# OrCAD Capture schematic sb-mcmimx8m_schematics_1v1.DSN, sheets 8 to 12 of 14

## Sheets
8 07. MIPI LCD: size A3; title: SBC-MCM-iMX8M   07. MIPI-LCD; rev: 2.0
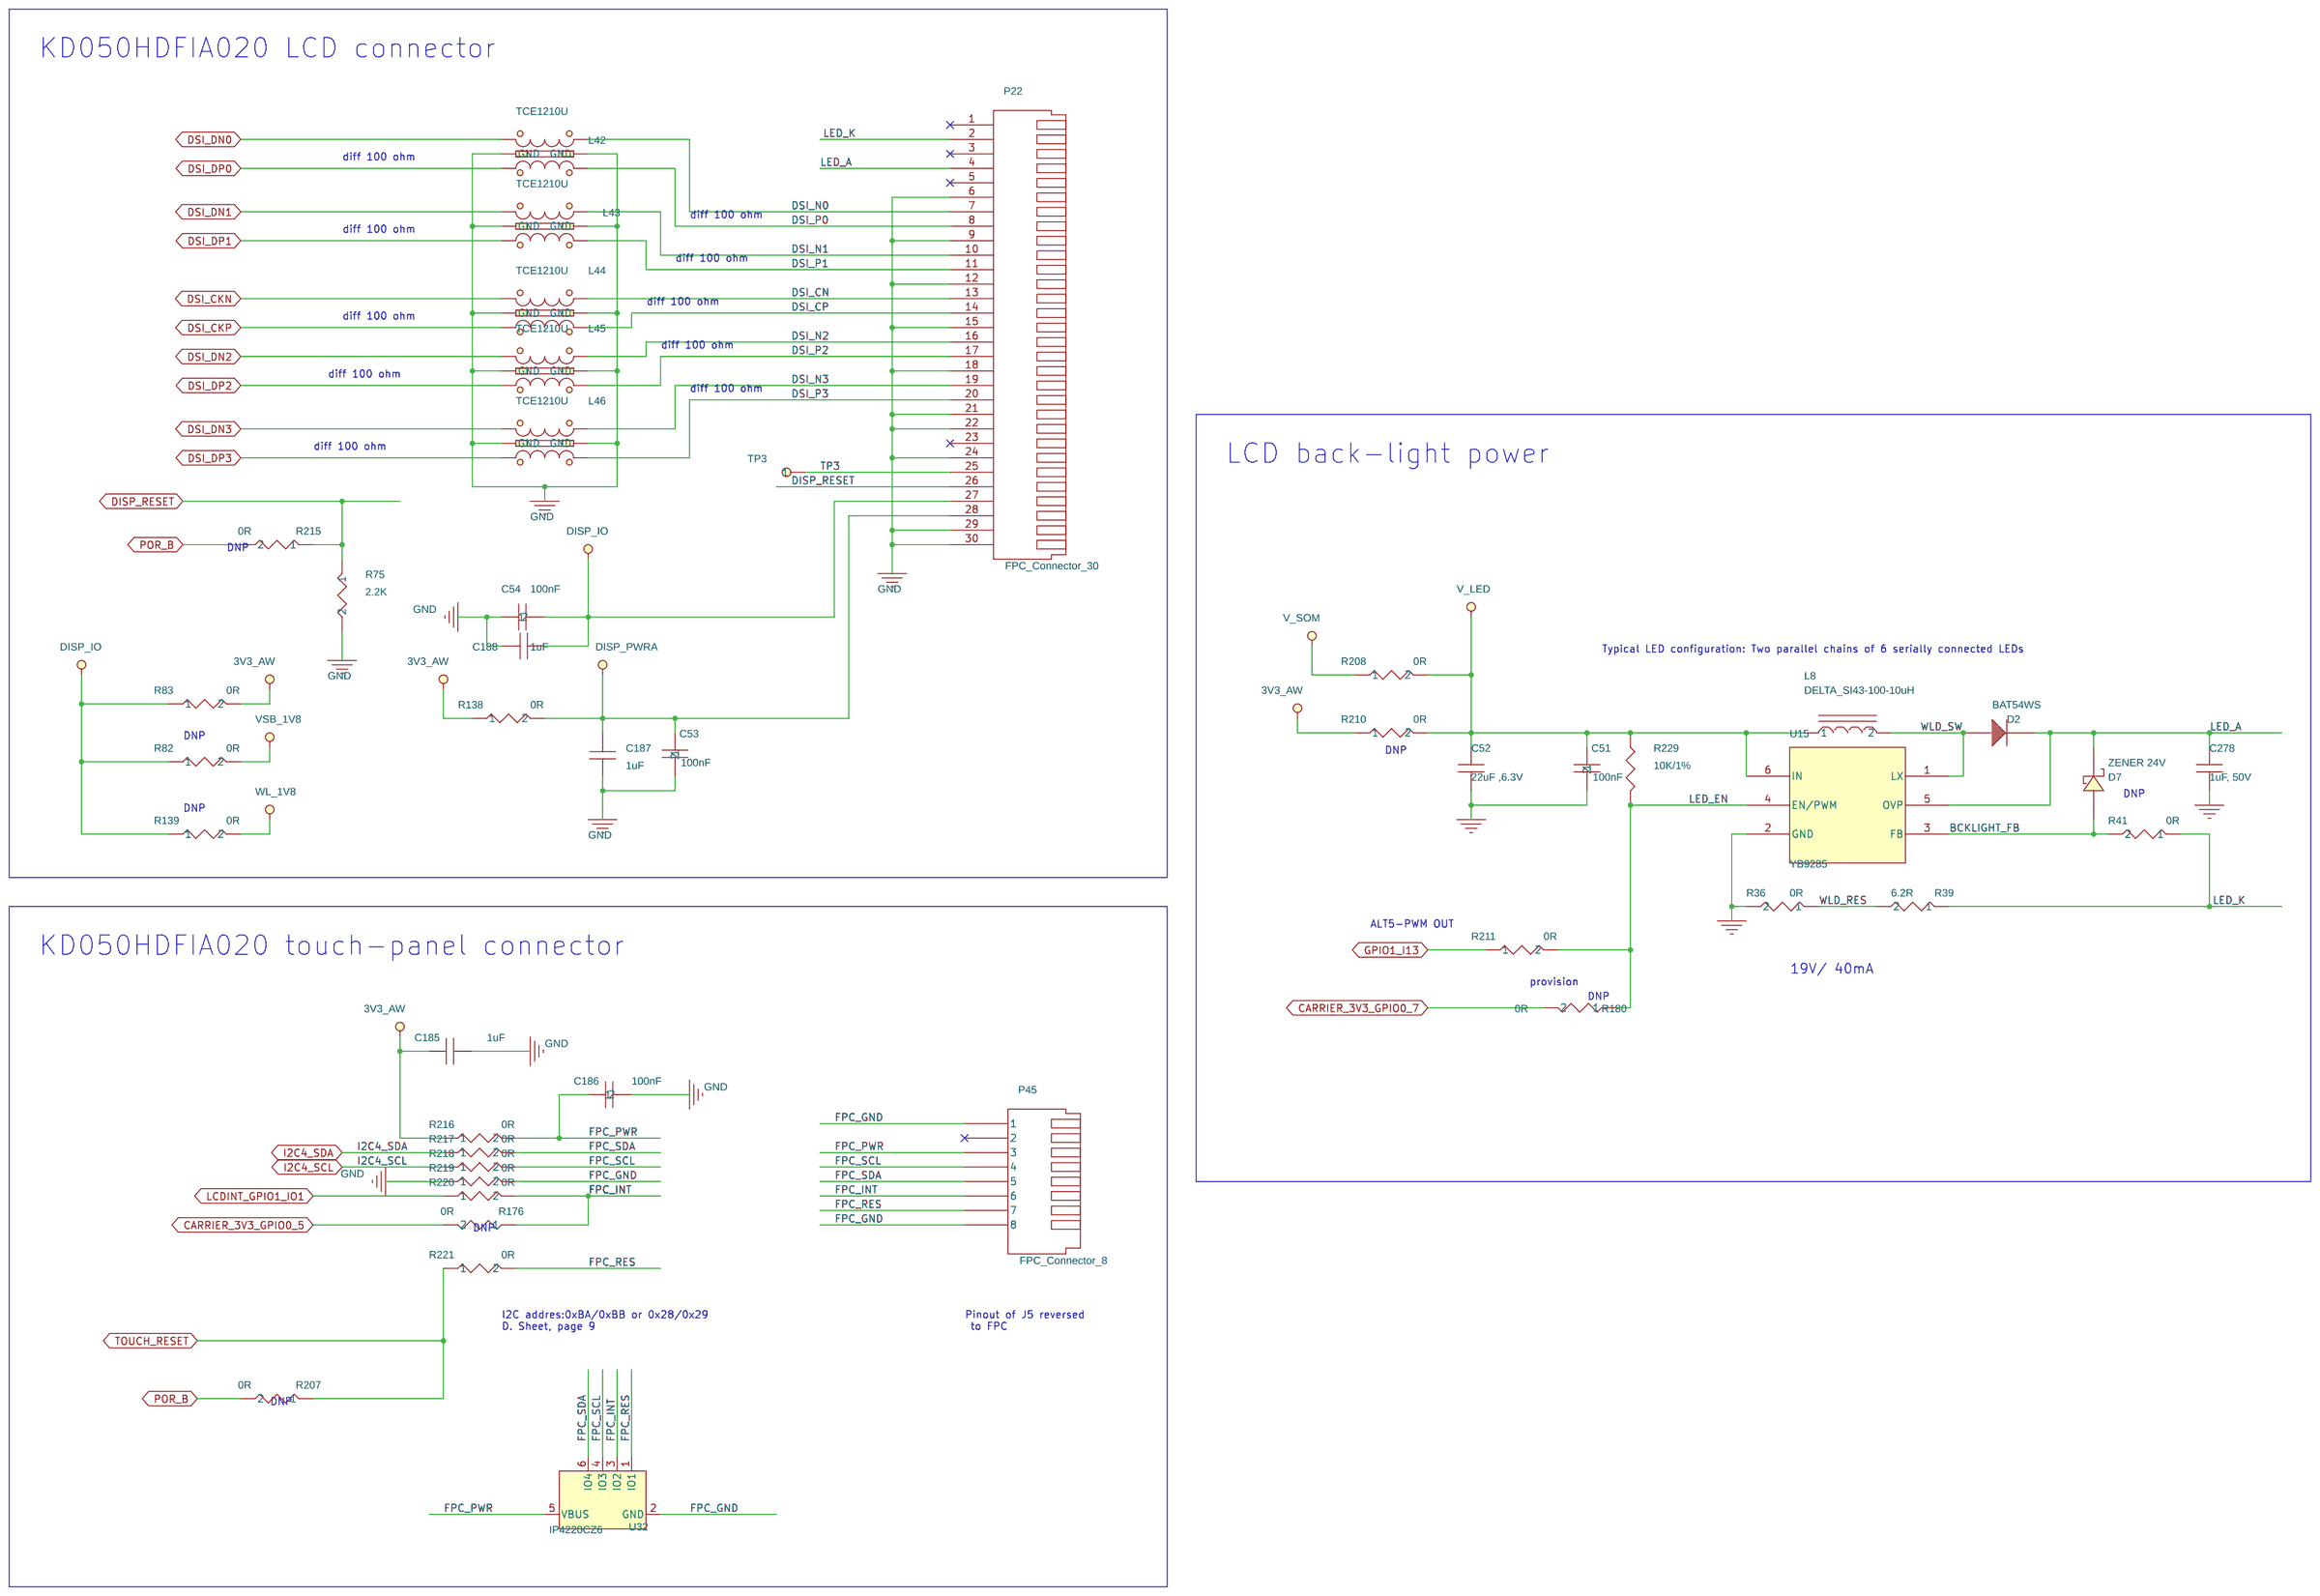
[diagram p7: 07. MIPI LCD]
9 08. PCIe: size A3; title: SB-UCM-iMX8M    08. PCIe; rev: 2.0
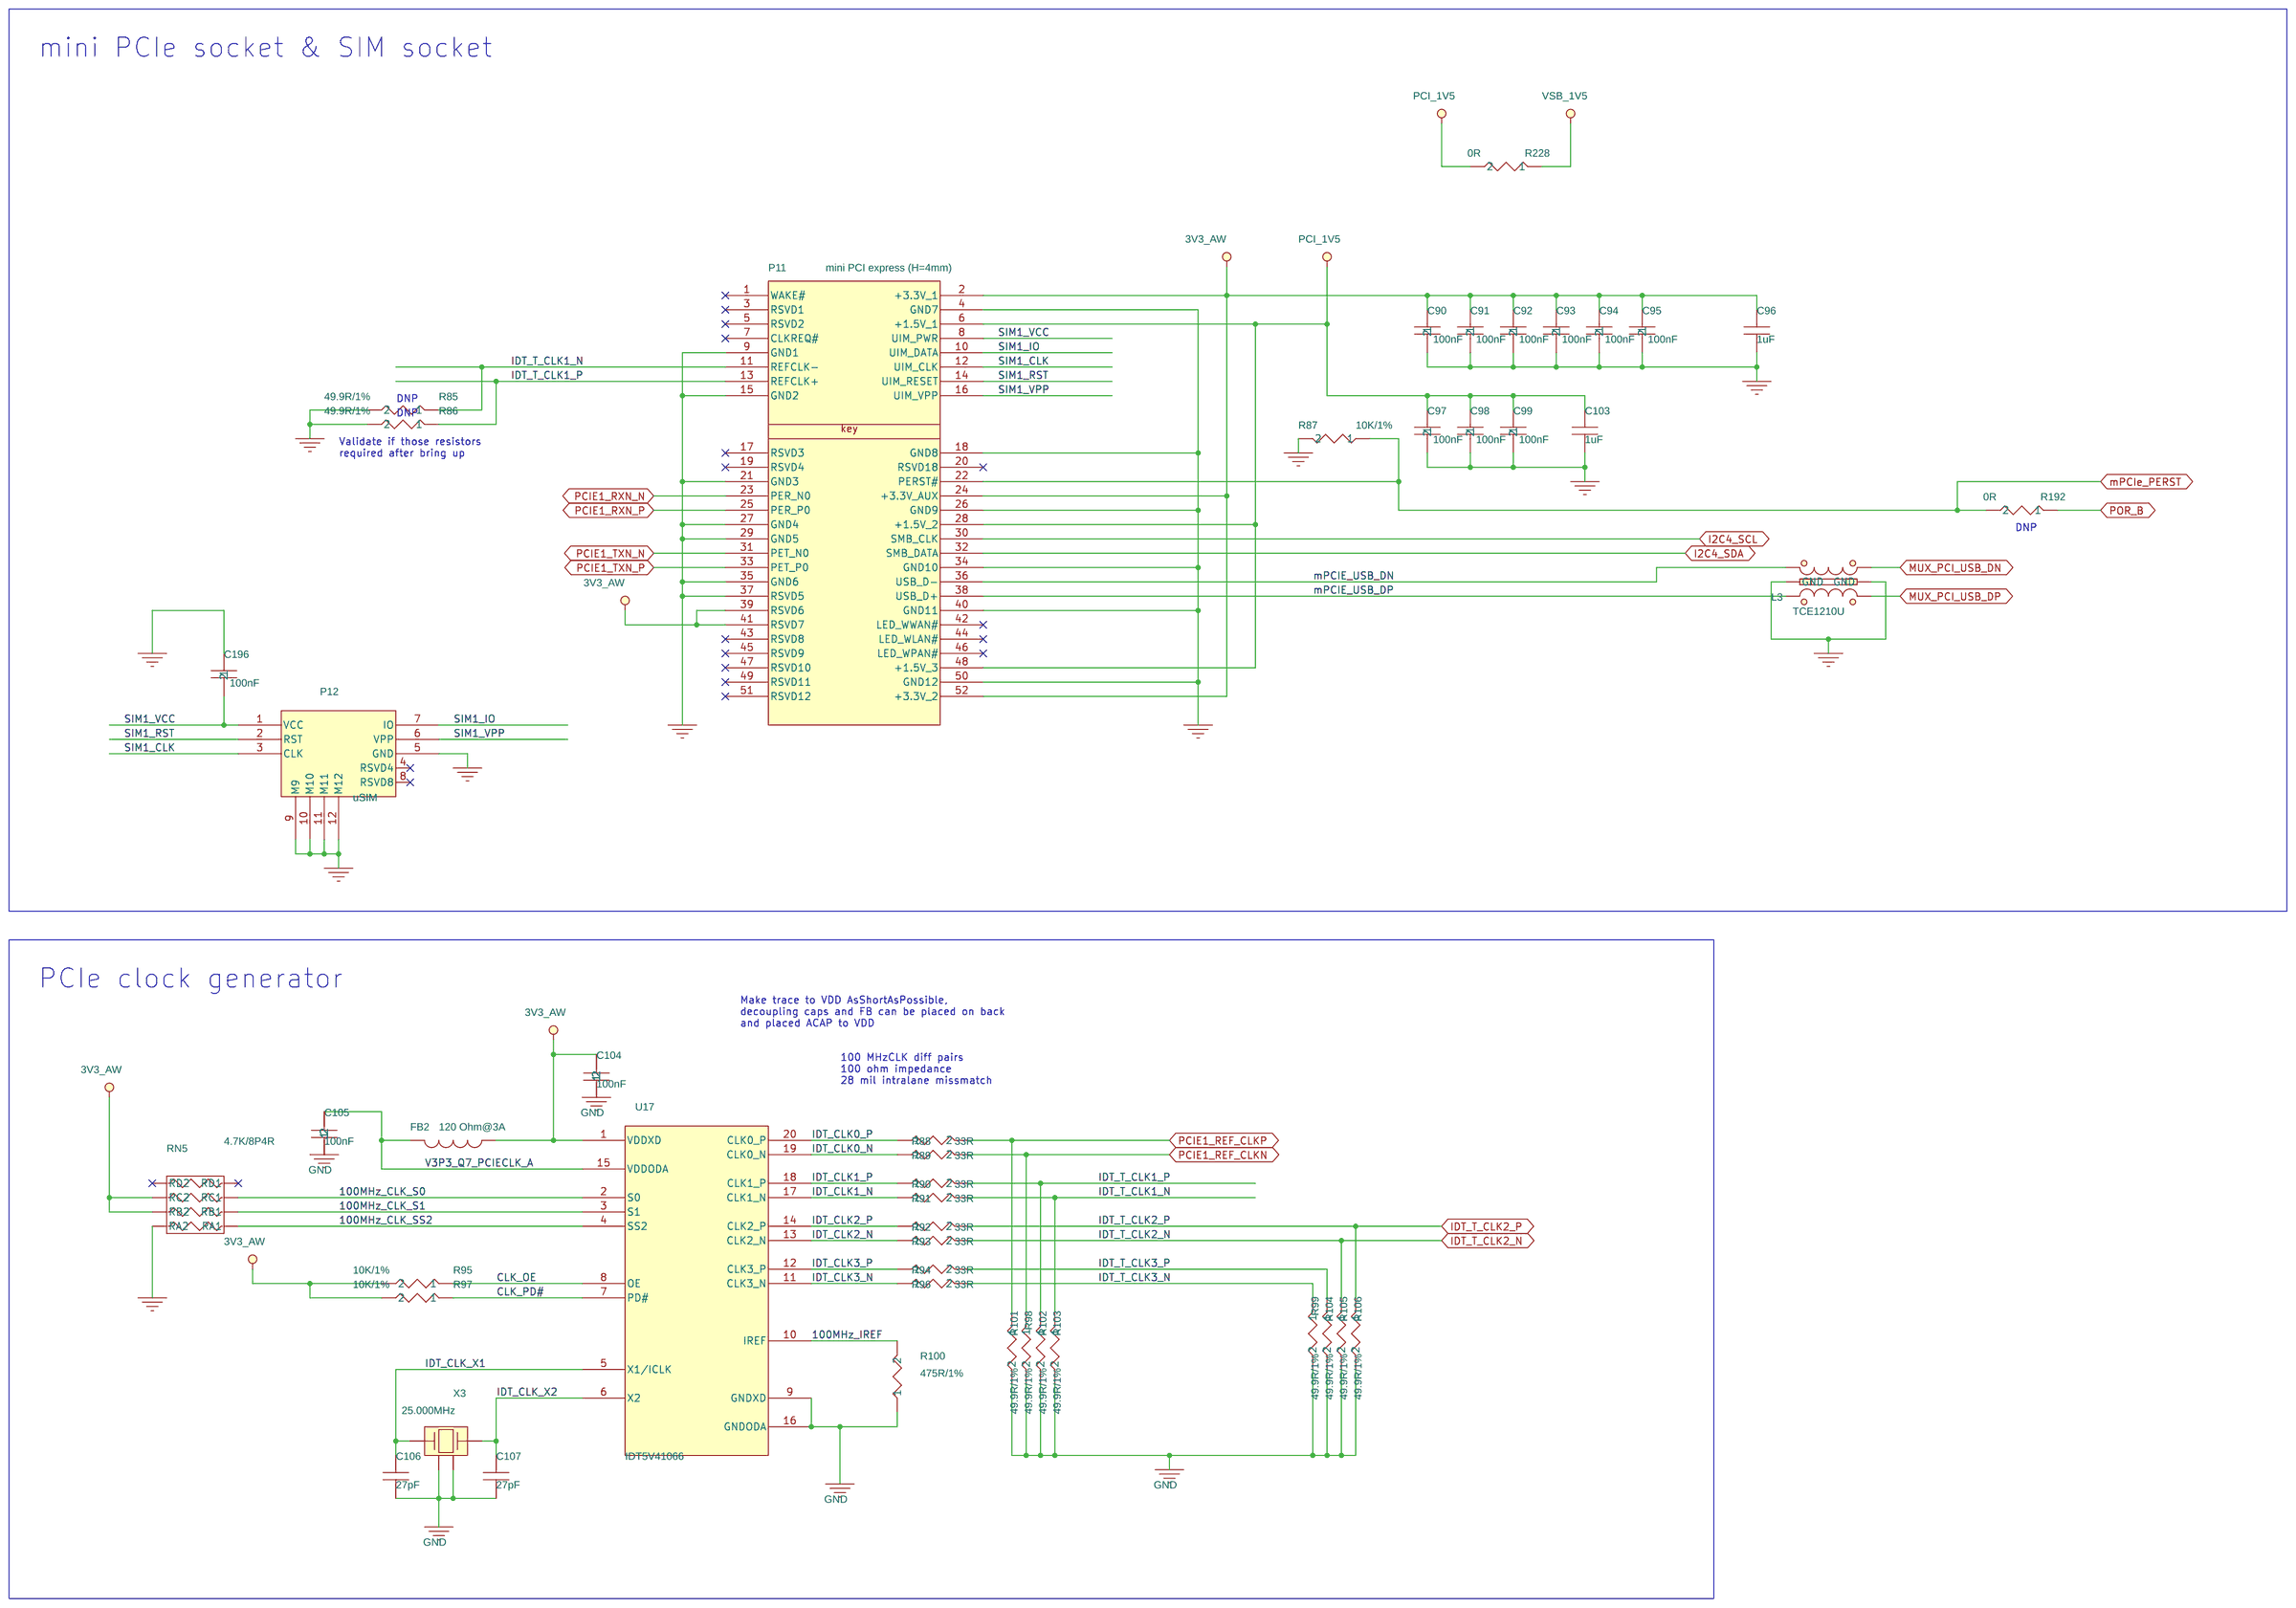
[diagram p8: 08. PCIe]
10 09. Power: size C; title: SBC-MCM-iMX8M    09. POWER; rev: 2.0
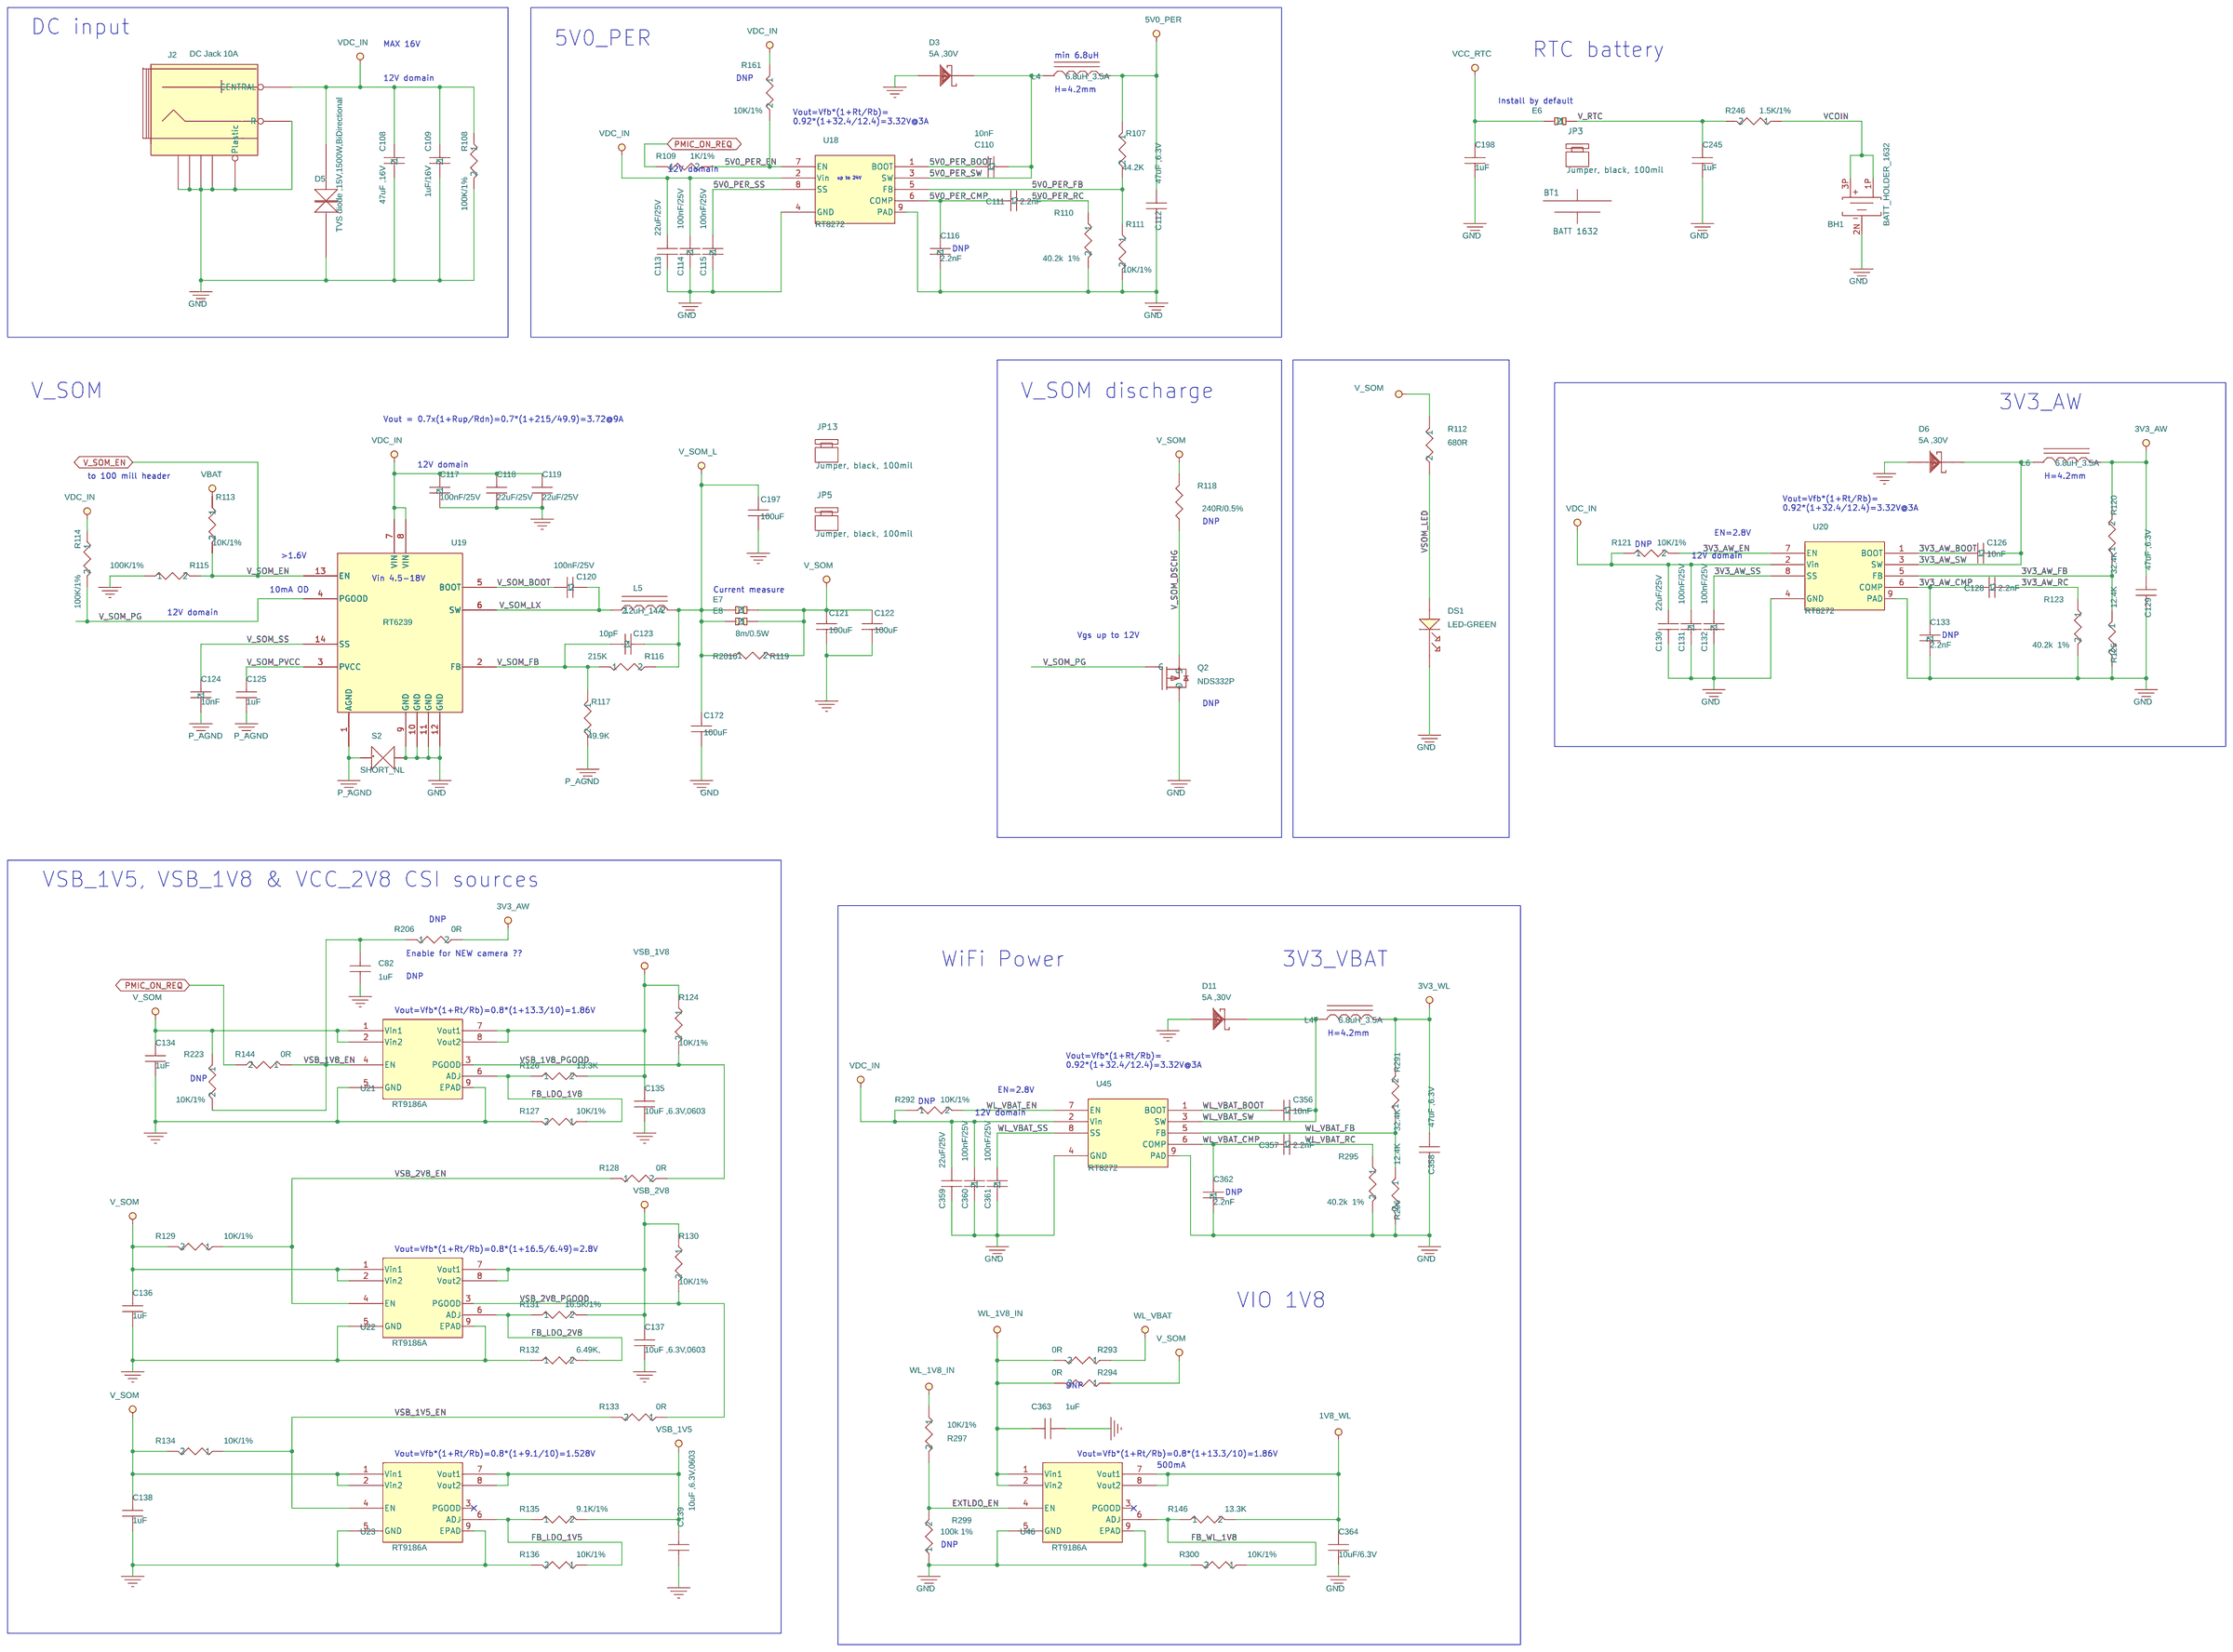
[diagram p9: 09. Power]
11 10. UART, RS232, SD, EPROM,QSPI: size C; title: SBC-MCM-iMX8M      10. UART, RS232, SD Slot, EEPROM,QSPI; rev: 2.0
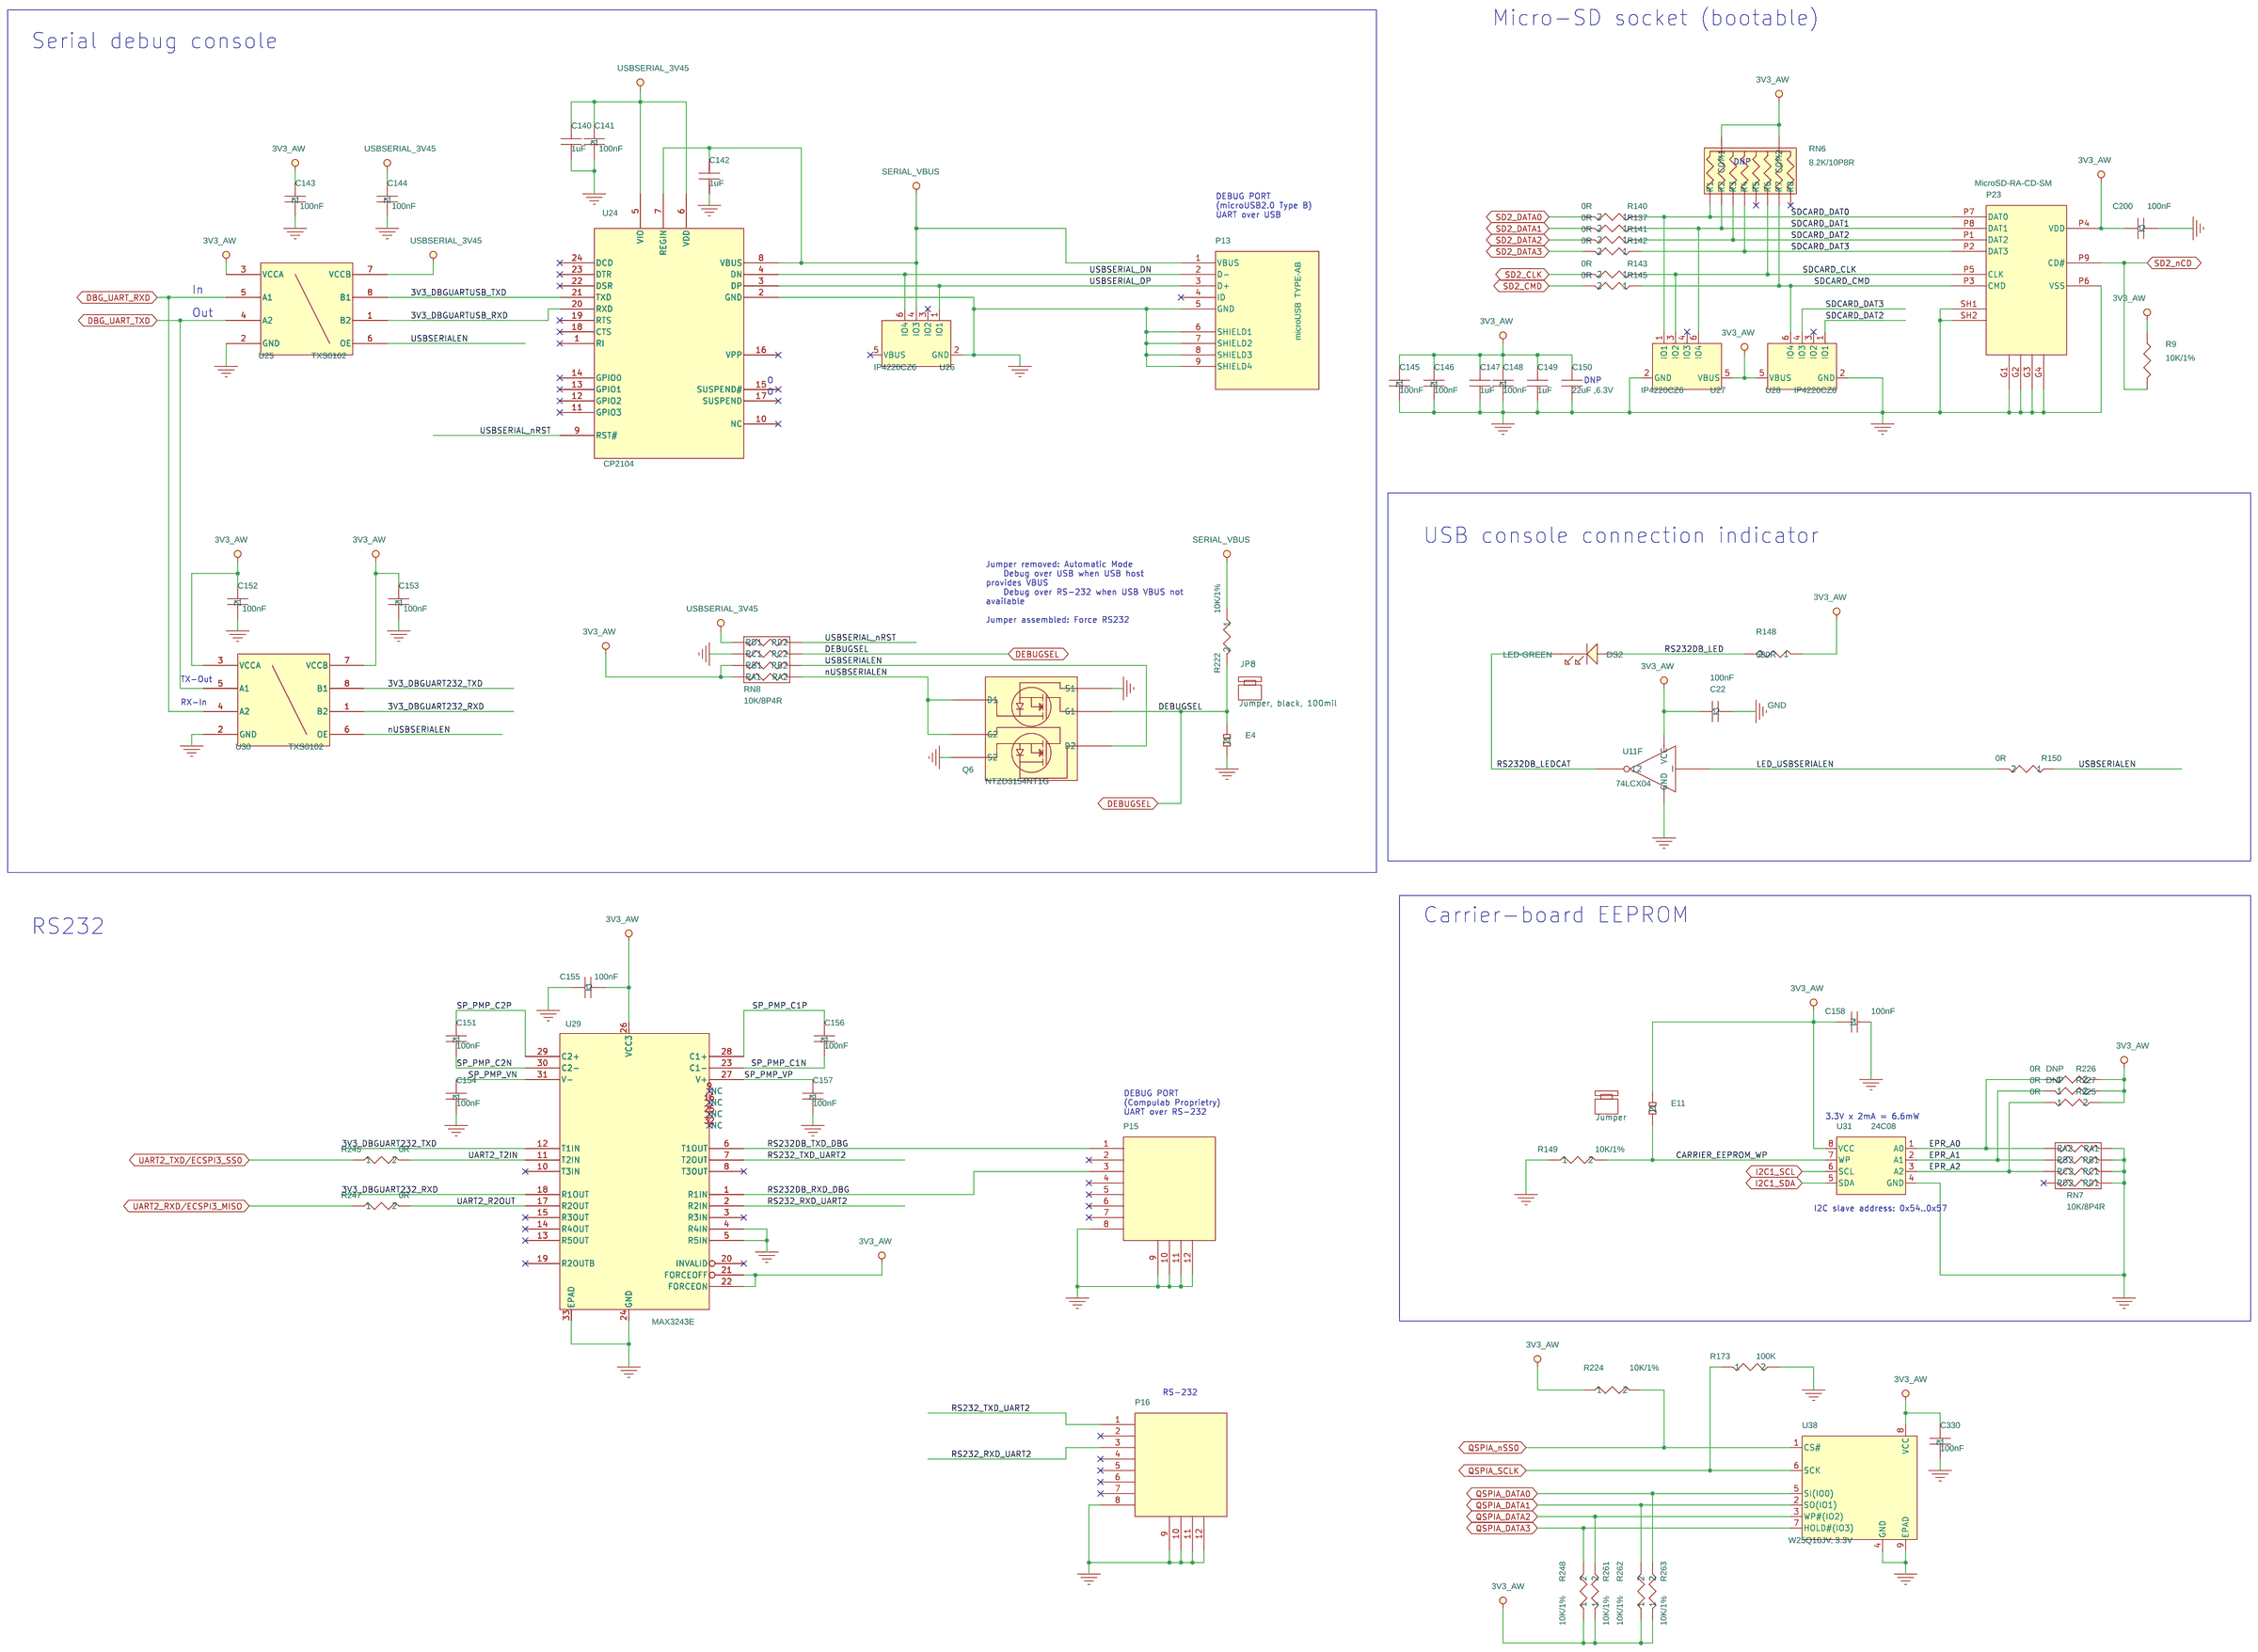
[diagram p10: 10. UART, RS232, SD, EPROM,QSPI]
12 11.WIFI&Bluetooth, RS485: size A2; title: SBC-MCM-iMX8M     11. WLAN,RS485
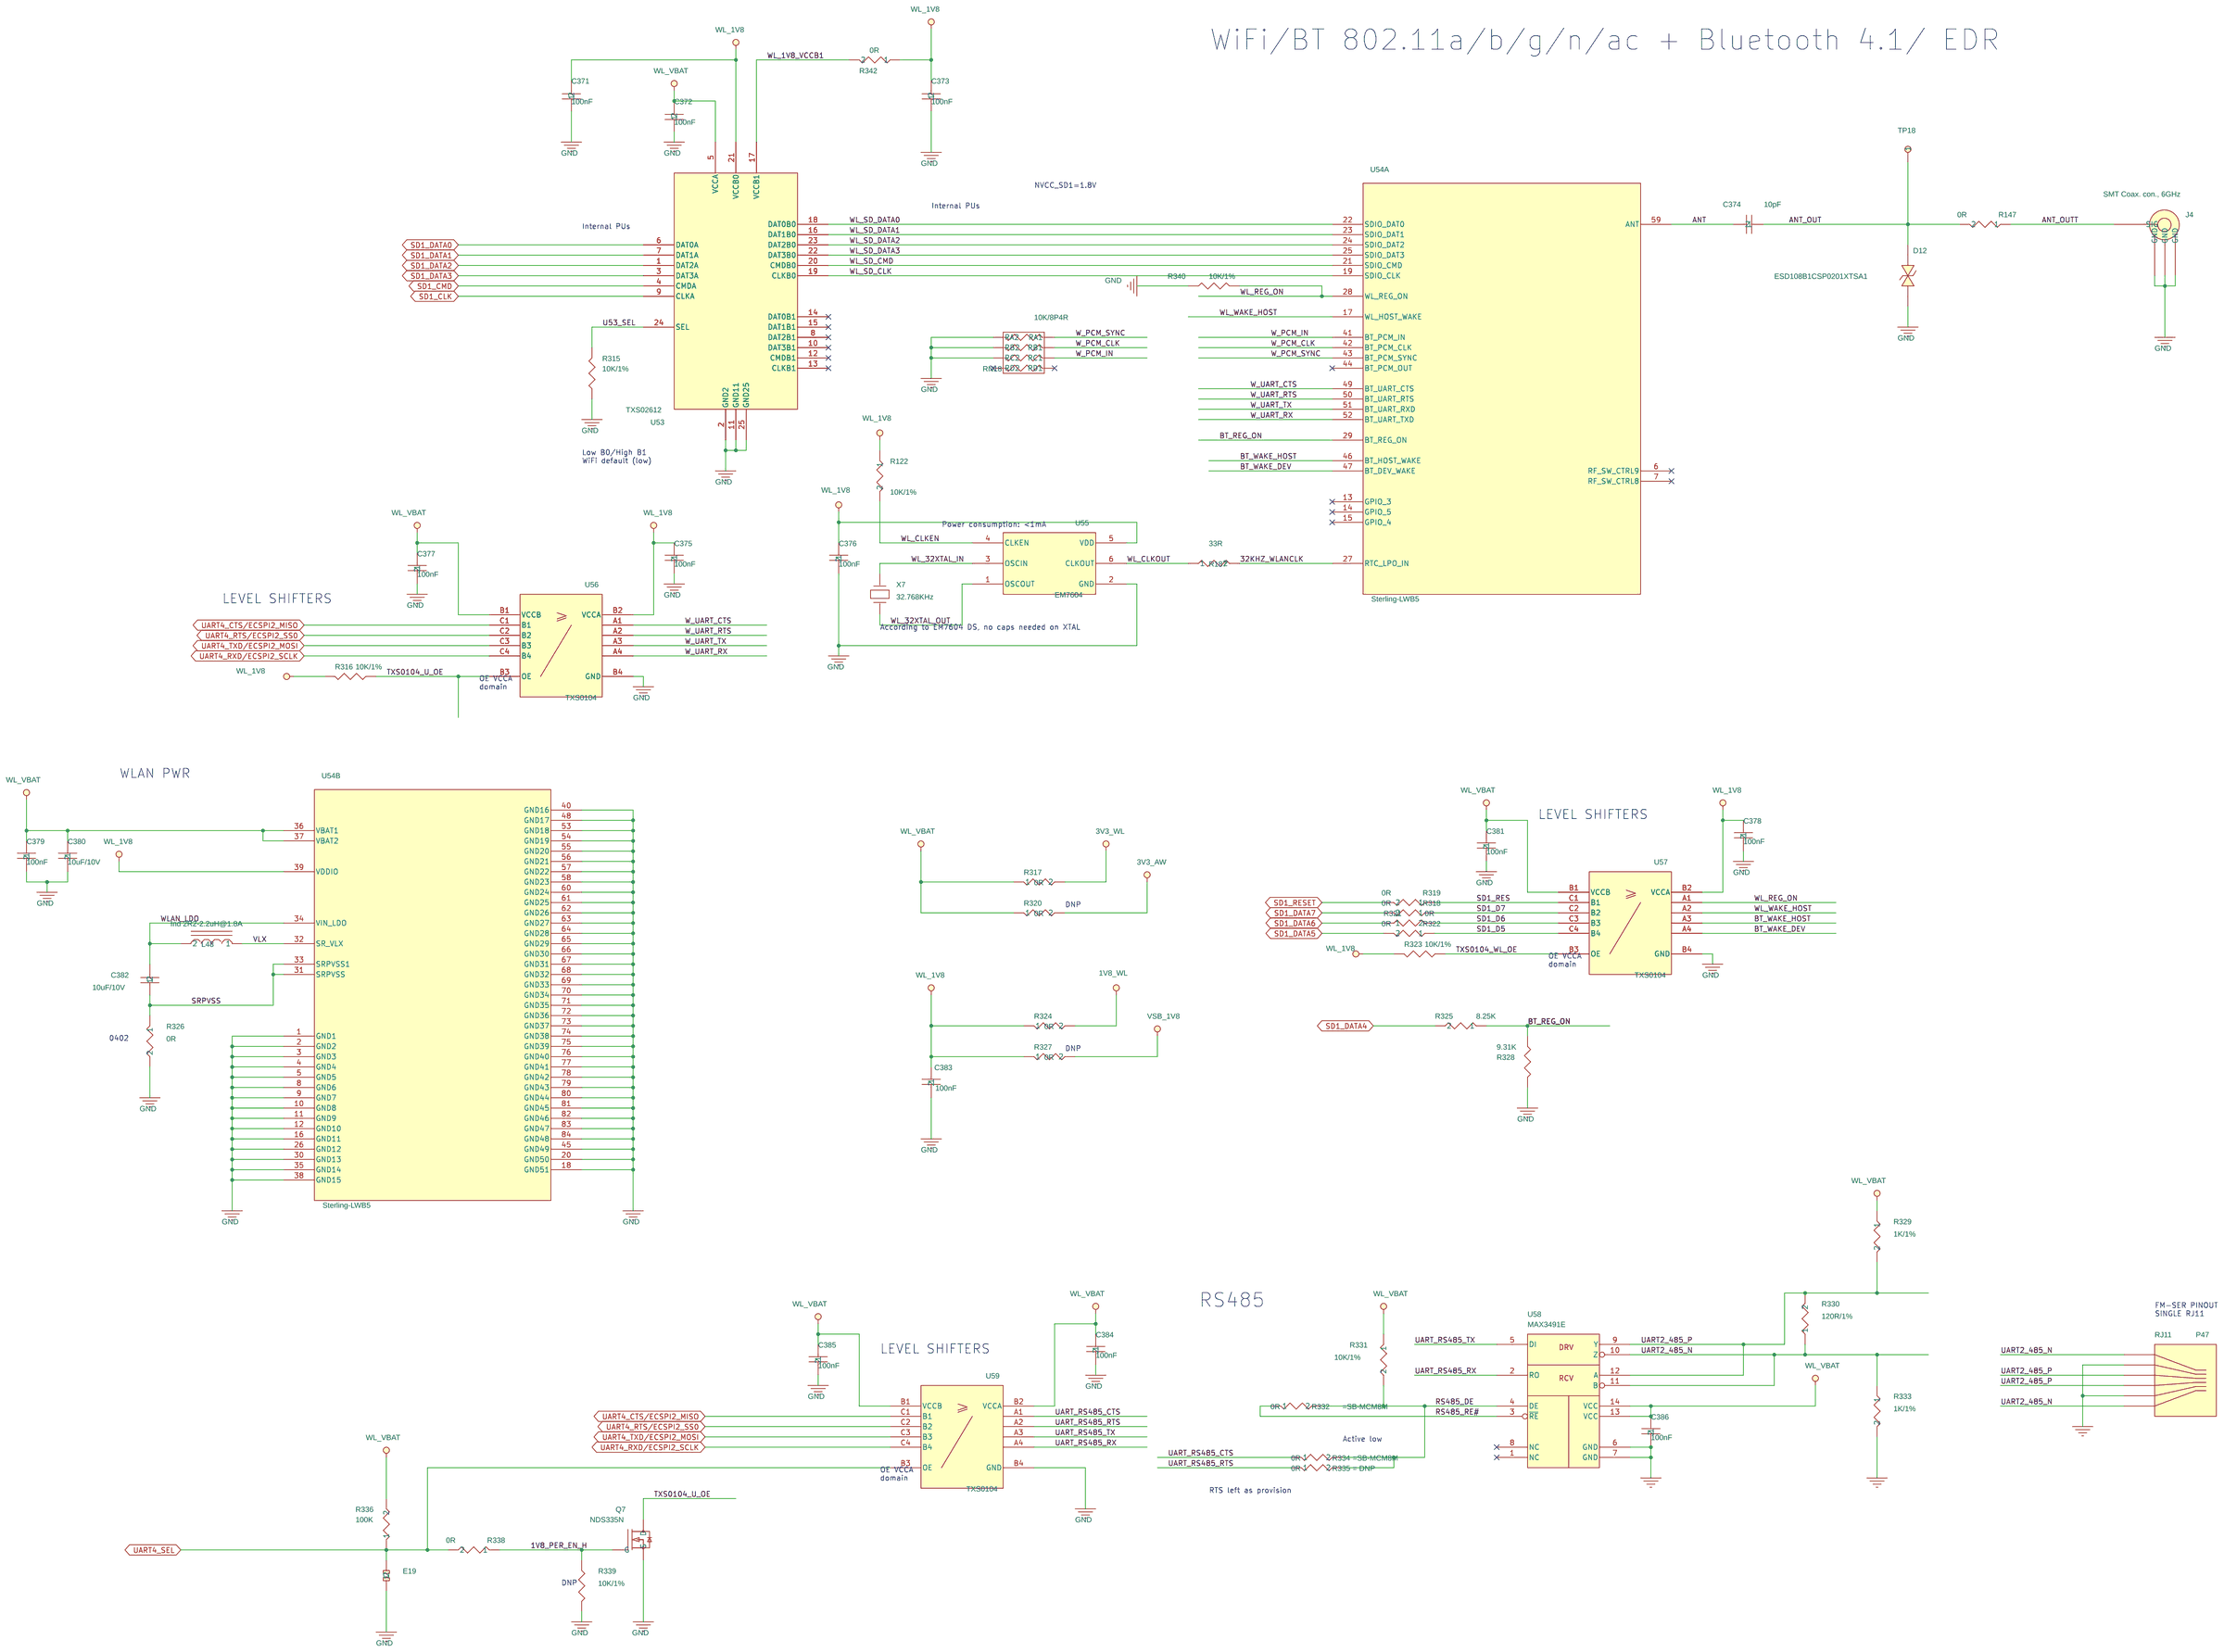
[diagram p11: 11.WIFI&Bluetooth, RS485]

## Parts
sheet 07. MIPI LCD
C51  100nF  [RC0402]
C52  22uF ,6.3V  [RC0603]
C53  100nF  [RC0402]
C54  100nF  [RC0402]
C185  1uF  [RC0402]
C186  100nF  [RC0402]
C187  1uF  [RC0402]
C188  1uF  [RC0402]
C278  1uF, 50V  [RC0603]
D2  BAT54WS  [SOD-323]
D7  ZENER 24V  [SOD-123]
L8  DELTA_SI43-100-10uH  [IND4x4x2_5]
L42  TCE1210U  [EMI1012-ESD]
L43  TCE1210U  [EMI1012-ESD]
L44  TCE1210U  [EMI1012-ESD]
L45  TCE1210U  [EMI1012-ESD]
L46  TCE1210U  [EMI1012-ESD]
P22  FPC_Connector_30  [FPC_30]
P45  FPC_Connector_8  [FPC_8]
R36  0R  [RC0402]
R39  6.2R  [RC0402]
R41  0R  [RC0402]
R75  2.2K  [RC0402]
R82  0R  [RC0402]
R83  0R  [RC0402]
R138  0R  [RC0402]
R139  0R  [RC0402]
R176  0R  [RC0402]
R180  0R  [RC0402]
R207  0R  [RC0402]
R208  0R  [RC0402]
R210  0R  [RC0402]
R211  0R  [RC0402]
R215  0R  [RC0402]
R216  0R  [RC0402]
R217  0R  [RC0402]
R218  0R  [RC0402]
R219  0R  [RC0402]
R220  0R  [RC0402]
R221  0R  [RC0402]
R229  10K/1%  [RC0402]
TP3  TESTPOINT  [TESTPOINT]
U15  YB9285  [SOT23-6L]
U32  IP4220CZ6  [SOT23-6L]
sheet 08. PCIe
C90  100nF  [RC0402]
C91  100nF  [RC0402]
C92  100nF  [RC0402]
C93  100nF  [RC0402]
C94  100nF  [RC0402]
C95  100nF  [RC0402]
C96  1uF  [RC0402]
C97  100nF  [RC0402]
C98  100nF  [RC0402]
C99  100nF  [RC0402]
C103  1uF  [RC0402]
C104  100nF  [RC0402]
C105  100nF  [RC0402]
C106  27pF  [RC0402]
C107  27pF  [RC0402]
C196  100nF  [RC0402]
FB2  120 Ohm@3A  [FB1206]
L3  TCE1210U  [EMI1012-ESD]
P11  mini PCI express (H=4mm)  [MINIPCIE-4]
P12  uSIM  [SKT-MicroSIM6-SM]
R85  49.9R/1%  [RC0402]
R86  49.9R/1%  [RC0402]
R87  10K/1%  [RC0402]
R88  33R  [RC0402]
R89  33R  [RC0402]
R90  33R  [RC0402]
R91  33R  [RC0402]
R92  33R  [RC0402]
R93  33R  [RC0402]
R94  33R  [RC0402]
R95  10K/1%  [RC0402]
R96  33R  [RC0402]
R97  10K/1%  [RC0402]
R98  49.9R/1%  [RC0402]
R99  49.9R/1%  [RC0402]
R100  475R/1%  [RC0402]
R101  49.9R/1%  [RC0402]
R102  49.9R/1%  [RC0402]
R103  49.9R/1%  [RC0402]
R104  49.9R/1%  [RC0402]
R105  49.9R/1%  [RC0402]
R106  49.9R/1%  [RC0402]
R192  0R  [RC0402]
R228  0R  [RC0402]
RN5  4.7K/8P4R  [RESNET8P0805]
U17  IDT5V41066  [TSSOP-20]
X3  25.000MHz  [OSC3225]
sheet 09. Power
BH1  BATT_HOLDER_1632  [BattH16mm-SM]
BT1  BATT 1632
C82  1uF  [RC0402]
C108  47uF ,16V  [C1210H2_5]
C109  1uF/16V  [RC0805]
C110  10nF  [RC0402]
C111  2.2nF  [RC0402]
C112  47uF ,6.3V  [C0805]
C113  22uF/25V  [C0805]
C114  100nF/25V  [RC0402]
C115  100nF/25V  [RC0402]
C116  2.2nF  [RC0402]
C117  100nF/25V  [RC0402]
C118  22uF/25V  [C0805]
C119  22uF/25V  [C0805]
C120  100nF/25V  [RC0402]
C121  100uF  [C1210H2_5]
C122  100uF  [C1210H2_5]
C123  10pF  [RC0402]
C124  10nF  [RC0402]
C125  1uF  [RC0402]
C126  10nF  [RC0402]
C128  2.2nF  [RC0402]
C129  47uF ,6.3V  [C0805]
C130  22uF/25V  [C0805]
C131  100nF/25V  [RC0402]
C132  100nF/25V  [RC0402]
C133  2.2nF  [RC0402]
C134  1uF  [RC0402]
C135  10uF ,6.3V,0603  [C0603-08]
C136  1uF  [RC0402]
C137  10uF ,6.3V,0603  [C0603-08]
C138  1uF  [RC0402]
C139  10uF ,6.3V,0603  [C0603-08]
C172  100uF  [C1210H2_5]
C197  100uF  [C1210H2_5]
C198  1uF  [RC0402]
C245  1uF  [RC0402]
C356  10nF  [RC0402]
C357  2.2nF  [RC0402]
C358  47uF ,6.3V  [C0805]
C359  22uF/25V  [C0805]
C360  100nF/25V  [RC0402]
C361  100nF/25V  [RC0402]
C362  2.2nF  [RC0402]
C363  1uF  [RC0402]
C364  10uF/6.3V  [C0603-08]
D3  5A ,30V  [SOD-128]
D5  TVS diode ,15V,1500W,BiDirectional  [DO-214AB]
D6  5A ,30V  [SOD-128]
D11  5A ,30V  [SOD-128]
DS1  LED-GREEN  [LED-1206]
E6  HDR1X2  [1X2THHDR]
E7  HDR1X2  [1X2THHDR]
E8  HDR1X2  [1X2THHDR]
J2  DC Jack 10A  [PJ-0810-TH]
JP3  Jumper, black, 100mil
JP5  Jumper, black, 100mil
JP13  Jumper, black, 100mil
L4  6.8uH_3.5A  [IND8_2x8_2]
L5  2.2uH_14A  [IND7x7_2SM]
L6  6.8uH_3.5A  [IND8_2x8_2]
L47  6.8uH_3.5A  [IND8_2x8_2]
Q2  NDS332P  [SOT23]
R107  44.2K  [RC0402]
R108  100K/1%  [RC0402]
R109  1K/1%  [RC0402]
R110  40.2k  1%  [RC0402]
R111  10K/1%  [RC0402]
R112  680R  [RC0402]
R113  10K/1%  [RC0402]
R114  100K/1%  [RC0402]
R115  100K/1%  [RC0402]
R116  215K  [RC0402]
R117  49.9K  [RC0402]
R118  240R/0.5%  [RC0402]
R119  8m/0.5W  [R2010]
R120  32.4K  [RC0402]
R121  10K/1%  [RC0402]
R123  40.2k  1%  [RC0402]
R124  10K/1%  [RC0402]
R125  12.4K  [RC0402]
R126  13.3K  [RC0402]
R127  10K/1%  [RC0402]
R128  0R  [RC0402]
R129  10K/1%  [RC0402]
R130  10K/1%  [RC0402]
R131  16.5K/1%  [RC0402]
R132  6.49K,  [RC0402]
R133  0R  [RC0402]
R134  10K/1%  [RC0402]
R135  9.1K/1%  [RC0402]
R136  10K/1%  [RC0402]
R144  0R  [RC0402]
R146  13.3K  [RC0402]
R161  10K/1%  [RC0402]
R206  0R  [RC0402]
R223  10K/1%  [RC0402]
R246  1.5K/1%  [RC0402]
R291  32.4K  [RC0402]
R292  10K/1%  [RC0402]
R293  0R  [RC0402]
R294  0R  [RC0402]
R295  40.2k  1%  [RC0402]
R296  12.4K  [RC0402]
R297  10K/1%  [RC0402]
R299  100k 1%  [RC0402]
R300  10K/1%  [RC0402]
S2  SHORT_NL  [SHORT_NL]
U18  RT8272  [PSOP-8-2X2]
U19  RT6239  [uQFN2x3-14]
U20  RT8272  [PSOP-8-2X2]
U21  RT9186A  [DFN3x3-8]
U22  RT9186A  [DFN3x3-8]
U23  RT9186A  [DFN3x3-8]
U45  RT8272  [PSOP-8-2X2]
U46  RT9186A  [DFN3x3-8]
sheet 10. UART, RS232, SD, EPROM,QSPI
C22  100nF  [RC0402]
C140  1uF  [RC0402]
C141  100nF  [RC0402]
C142  1uF  [RC0402]
C143  100nF  [RC0402]
C144  100nF  [RC0402]
C145  100nF  [RC0402]
C146  100nF  [RC0402]
C147  1uF  [RC0402]
C148  100nF  [RC0402]
C149  1uF  [RC0402]
C150  22uF ,6.3V  [RC0603]
C151  100nF  [RC0402]
C152  100nF  [RC0402]
C153  100nF  [RC0402]
C154  100nF  [RC0402]
C155  100nF  [RC0402]
C156  100nF  [RC0402]
C157  100nF  [RC0402]
C158  100nF  [RC0402]
C200  100nF  [RC0402]
C330  100nF  [RC0402]
DS2  LED-GREEN  [LED-1206]
E4  HDR1X2  [1X2THHDR]
E11  HDR1X2  [1X2THHDR]
JP6  Jumper
JP8  Jumper, black, 100mil
P13  microUSB  TYPE-AB  [MICRO-USB-AB-RA-SM]
P15  Ultra Mini Serial Connector  [UMS-8]
P16  Ultra Mini Serial Connector  [UMS-8]
P23  MicroSD-RA-CD-SM  [MicroSD-RA-CD-SM]
Q6  NTZD3154NT1G  [SOT-563]
R9  10K/1%  [RC0402]
R137  0R  [RC0402]
R140  0R  [RC0402]
R141  0R  [RC0402]
R142  0R  [RC0402]
R143  0R  [RC0402]
R145  0R  [RC0402]
R148  680R  [RC0402]
R149  10K/1%  [RC0402]
R150  0R  [RC0402]
R173  100K  [RC0402]
R222  10K/1%  [RC0402]
R224  10K/1%  [RC0402]
R225  0R  [RC0402]
R226  0R  [RC0402]
R227  0R  [RC0402]
R245  0R  [RC0402]
R247  0R  [RC0402]
R248  10K/1%  [RC0402]
R261  10K/1%  [RC0402]
R262  10K/1%  [RC0402]
R263  10K/1%  [RC0402]
RN6  8.2K/10P8R  [RESNET10P1206]
RN7  10K/8P4R  [RESNET8P0805]
RN8  10K/8P4R  [RESNET8P0805]
U11  74LCX04  [TSSOP-14]  (sections A,B,C,D,E,F)
U24  CP2104  [MO-220VGGD-8]
U25  TXS0102  [MO-187DA-8]
U26  IP4220CZ6  [SOT23-6L]
U27  IP4220CZ6  [SOT23-6L]
U28  IP4220CZ6  [SOT23-6L]
U29  MAX3243E  [QFN5x5-32]
U30  TXS0102  [MO-187DA-8]
U31  24C08  [MO-229VCED-2]
U38  W25Q16JV, 3.3V  [WSON5x6-8]
sheet 11.WIFI&Bluetooth, RS485
C371  100nF  [RC0402]
C372  100nF  [RC0402]
C373  100nF  [RC0402]
C374  10pF  [RC0402]
C375  100nF  [RC0402]
C376  100nF  [RC0402]
C377  100nF  [RC0402]
C378  100nF  [RC0402]
C379  100nF  [RC0402]
C380  10uF/10V  [0402]
C381  100nF  [RC0402]
C382  10uF/10V  [0402]
C383  100nF  [RC0402]
C384  100nF  [RC0402]
C385  100nF  [RC0402]
C386  100nF  [RC0402]
D12  ESD108B1CSP0201XTSA1
E19  HDR1X2  [1X2THHDR]
J4  SMT Coax. con., 6GHz  [CX-R2x2x0_8S]
L48  Ind 2R2-2.2uH@1.8A  [Ind2x2_5x1_2]
P47  RJ11  [RJ11TH6-6]
Q7  NDS335N  [SOT23]
R122  10K/1%  [RC0402]
R147  0R  [RC0402]
R187  33R  [RC0402]
R315  10K/1%  [RC0402]
R316  10K/1%  [RC0402]
R317  0R  [RC0402]
R318  0R  [RC0402]
R319  0R  [RC0402]
R320  0R  [RC0402]
R321  0R  [RC0402]
R322  0R  [RC0402]
R323  10K/1%  [RC0402]
R324  0R  [RC0402]
R325  8.25K  [RC0402]
R326  0R  [RC0402]
R327  0R  [RC0402]
R328  9.31K  [RC0402]
R329  1K/1%  [RC0402]
R330  120R/1%  [RC0603]
R331  10K/1%  [RC0402]
R332  0R  [RC0402]
R333  1K/1%  [RC0402]
R334  0R  [RC0402]
R335  0R  [RC0402]
R336  100K  [RC0402]
R338  0R  [RC0402]
R339  10K/1%  [RC0402]
R340  10K/1%  [RC0402]
R342  0R  [RC0402]
RN18  10K/8P4R  [RESNET8P0805]
TP18  TESTPOINT  [WL_TESTPOINT]
U53  TXS02612  [MO-220VGGD-8]
U54  Sterling-LWB5  (sections A,B)
U55  EM7604  [SOT23-6L]
U56  TXS0104  [BGA-12-05-2_1X2_6]
U57  TXS0104  [BGA-12-05-2_1X2_6]
U58  MAX3491E  [SO-14-150]
U59  TXS0104  [BGA-12-05-2_1X2_6]
X7  32.768KHz  [XTAL3_2x1_5]

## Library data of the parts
C51 C104 C145 C376 = 100nF,_10V,_X7R,_10%,_0402_3: CLABCONF0: =SB-MCM8M
C52 C150 = 22uF,6.3V,X5R: CLABCONF0: =SB-MCM8M; P/N: 151B22610S
C53 C92 C151 C379 = 100nF,_10V,_X7R,_10%,_0402: CLABCONF0: =SB-MCM8M
C54 C99 C200 C375 = 100nF,_10V,_X7R,_10%,_0402_1: CLABCONF0: =SB-MCM8M
C96 C103 C134 C136 C138 C140 C142 C147 C149 C185 C187 C188 C198 C245 C363 = 1uF,X5R,6.3V,0402: CLABCONF0: =SB-MCM8M
C95 C158 C186 = 100nF,_10V,_X7R,_10%,_0402_2: CLABCONF0: =SB-MCM8M
C278 = 1uF,X5R,6.3V,0402: CLABCONF0: =SB-MCM8M; P/N: 151D10510S
D2 = BAT54WS_0: CLABCONF0: =SB-MCM8M
D7 = ZENER_24V_500mW_SOD-123: CLABCONF0: DNP
L8 = INC_DELTA_SI43-100,_10uH: CLABCONF0: =SB-MCM8M; CLABCONF1: <null>; CLABCONF2: <null>; CLABCONF3: <null>; CLABCONF4: <null>; CLABCONF5: <null>; CLABCONF6: <null>; CLABCONF7: <null>; CLABCONF8: <null>; CLABCONF9: <null>
L3 L42-L46 = ESD_CHOKE_DIFFx2_10: CLABCONF0: =SB-MCM8M; P/N: 142D11801S
P22 = FPC_Connector_30: CLABCONF0: =SB-MCM8M; P/N: 182P03002S
P45 = FPC_Connector_8: CLABCONF0: =SB-MCM8M; P/N: 182P00802S
R36 = 2.2R,5%,0402,1_16W: CLABCONF0: =SB-MCM8M; P/N: 161C00005S
R39 = 2.2R,5%,0402,1_16W_1: CLABCONF0: =SB-MCM8M; P/N: 161C06R25S
R41 = 0R,_0402_9: CLABCONF0: =SB-MCM8M
R75 = 2.2K,5%,0402.1_16W: CLABCONF0: =SB-MCM8M
R82 = 0R,_0402_4: CLABCONF0: DNP
R83 = 0R,_0402_11: CLABCONF0: =SB-MCM8M
R138 = 0R,_0402_7: CLABCONF0: =SB-MCM8M
R139 R176 = 0R,_0402_1: CLABCONF0: DNP
R180 = 0R,_0402_1_1: CLABCONF0: DNP
R207 = 0R,_0402_0_1: CLABCONF0: DNP; P/N: 161C00005S
R208 = 0R,_0402_12: CLABCONF0: =SB-MCM8M
R210 = 0R,_0402_3: CLABCONF0: DNP
R211 = 0R,_0402_5: CLABCONF0: =SB-MCM8M
R192 R215 = 0R,_0402_0: CLABCONF0: DNP; P/N: 161C00005S
R216 = 0R,_0402_2: CLABCONF0: =SB-MCM8M
R217 = 0R,_0402_6: CLABCONF0: =SB-MCM8M
R218 = 0R,_0402_8: CLABCONF0: =SB-MCM8M
R219 = 0R,_0402_10: CLABCONF0: =SB-MCM8M
R220 = 0R,_0402_13: CLABCONF0: =SB-MCM8M
R221 R245 R321 = 0R,_0402: CLABCONF0: =SB-MCM8M
R9 R229 = 10K,1%,0402,1_16W_0: CLABCONF0: =SB-MCM8M
TP3 TP18 = TESTPOINT: CLABCONF0: DNP
U15 = AIC1647_0: CLABCONF0: =SB-MCM8M; P/N: 123C40000S
U26-U28 U32 = IP4220CZ6_0: CLABCONF0: =SB-MCM8M
C22 C90 C377 = 100nF,_10V,_X7R,_10%,_0402_5: CLABCONF0: =SB-MCM8M
C91 C148 C378 = 100nF,_10V,_X7R,_10%,_0402_8: CLABCONF0: =SB-MCM8M
C93 C154 C386 = 100nF,_10V,_X7R,_10%,_0402_7: CLABCONF0: =SB-MCM8M
C94 C146 C385 = 100nF,_10V,_X7R,_10%,_0402_10: CLABCONF0: =SB-MCM8M
C97 C143 C384 = 100nF,_10V,_X7R,_10%,_0402_6: CLABCONF0: =SB-MCM8M
C98 C141 C383 = 100nF,_10V,_X7R,_10%,_0402_9: CLABCONF0: =SB-MCM8M
C105 C157 = 100nF,_10V,_X7R,_10%,_0402_4: CLABCONF0: =SB-MCM8M
C106 C107 = 27pF,_50V,_X7R,_10%,_0402: CLABCONF0: =SB-MCM8M; P/N: 151D27000S
C153 C196 = 100nF,_10V,_X7R,_10%,_0402_11: CLABCONF0: =SB-MCM8M
FB2 = Ferrite_bead_,_120_Ohm@3A: CLABCONF0: =SB-MCM8M
P11 = mini_PCIe_0: CLABCONF0: =SB-MCM8M; P/N: 182K05201S
P12 = uSIM_SOCKET_0: CLABCONF0: =SB-MCM8M
R85 = 49.9R_1%,_0402_3: CLABCONF0: DNP
R86 = 49.9R_1%,_0402_4: CLABCONF0: DNP
R87 R261 = 10K,1%,0402,1_16W_2: CLABCONF0: =SB-MCM8M
R88 = 33R,5%,0402,1_16W_1: CLABCONF0: =SB-MCM8M
R89 = 33R,5%,0402,1_16W_3: CLABCONF0: =SB-MCM8M
R90 = 33R,5%,0402,1_16W_6: CLABCONF0: =SB-MCM8M
R91 = 33R,5%,0402,1_16W_7: CLABCONF0: =SB-MCM8M
R92 R187 = 33R,5%,0402,1_16W: CLABCONF0: =SB-MCM8M
R93 = 33R,5%,0402,1_16W_2: CLABCONF0: =SB-MCM8M
R94 = 33R,5%,0402,1_16W_5: CLABCONF0: =SB-MCM8M
R95 R122 R248 R300 = 10K,1%,0402,1_16W: CLABCONF0: =SB-MCM8M
R96 = 33R,5%,0402,1_16W_4: CLABCONF0: =SB-MCM8M
R97 R113 R149 R331 = 10K,1%,0402,1_16W_1: CLABCONF0: =SB-MCM8M
R98 = 49.9R_1%,_0402_6: CLABCONF0: =SB-MCM8M
R99 = 49.9R_1%,_0402_9: CLABCONF0: =SB-MCM8M
R100 = 475R_1%,_0402: CLABCONF0: =SB-MCM8M
R101 = 49.9R_1%,_0402_5: CLABCONF0: =SB-MCM8M
R102 = 49.9R_1%,_0402_8: CLABCONF0: =SB-MCM8M
R103 = 49.9R_1%,_0402: CLABCONF0: =SB-MCM8M
R104 = 49.9R_1%,_0402_1: CLABCONF0: =SB-MCM8M
R105 = 49.9R_1%,_0402_2: CLABCONF0: =SB-MCM8M
R106 = 49.9R_1%,_0402_7: CLABCONF0: =SB-MCM8M
R228 = 0R,_0402_0_1: CLABCONF0: =SB-MCM8M; P/N: 161C00005S
RN5 = RN,4.7K,8P4R@0805: CLABCONF0: =SB-MCM8M
U17 = IDT5V41066_0: CLABCONF0: =SB-MCM8M; P/N: 116A00120S
X3 = XTAL,_25.000Mhz,_3x5mm: CLABCONF0: =SB-MCM8M; P/N: 141B25603I
BH1 = BATT_HOLDER_1: CLABCONF0: =SB-MCM8M; P/N: 190Z00300S
BT1 = BATT_2032: CLABCONF0: =SB-MCM8M; P/N: 210C30006
C82 = 1uF,X5R,6.3V,0402: CLABCONF0: DNP
C108 = Cap.,_47uF,_16V,_X5R: CLABCONF0: =SB-MCM8M
C109 = 1uF,_16V,_X7R,_20%,_0805: CLABCONF0: =SB-MCM8M
C110 = 10nF,_25V,_X7R,_10%,_0402_2: CLABCONF0: =SB-MCM8M
C111 = 2.2nF,_50V,_X7R,_10%,_0402: CLABCONF0: =SB-MCM8M
C112 = 47uF,6.3V,X5R_1: CLABCONF0: =SB-MCM8M
C113 = Cap.,22uF,25V,_0805_1: CLABCONF0: =SB-MCM8M
C114 = 100nF_0402_25V_7: CLABCONF0: =SB-MCM8M
C115 = 100nF_0402_25V_2: CLABCONF0: =SB-MCM8M
C116 = 2.2nF,_50V,_X7R,_10%,_0402_2: CLABCONF0: DNP
C117 = 100nF_0402_25V: CLABCONF0: =SB-MCM8M
C118 = 22uF,25V,_0805: CLABCONF0: =SB-MCM8M
C119 = 22uF,25V,_0805_1: CLABCONF0: =SB-MCM8M
C120 = 100nF_0402_25V_5: CLABCONF0: =SB-MCM8M
C121 C122 C172 C197 = 100uF,_6.3V,_X5R,_20%,_1206: CLABCONF0: =SB-MCM8M
C123 C374 = 10pF,50V,NPO,_5%,_0402: CLABCONF0: =SB-MCM8M
C124 = 10nF,_25V,_X7R,_10%,_0402_1: CLABCONF0: =SB-MCM8M
C125 = 1uF,16V,0402: CLABCONF0: =SB-MCM8M
C126 = 10nF,_25V,_X7R,_10%,_0402_3: CLABCONF0: =SB-MCM8M
C128 = 2.2nF,_50V,_X7R,_10%,_0402_1: CLABCONF0: =SB-MCM8M
C129 = 47uF,6.3V,X5R_2: CLABCONF0: =SB-MCM8M
C130 = Cap.,22uF,25V,_0805_2: CLABCONF0: =SB-MCM8M
C131 = 100nF_0402_25V_6: CLABCONF0: =SB-MCM8M
C132 = 100nF_0402_25V_4: CLABCONF0: =SB-MCM8M
C133 = 2.2nF,_50V,_X7R,_10%,_0402_5: CLABCONF0: =SB-MCM8M
C135 C137 C139 C364 = 10uF,6_0.3V,0603,20%X5R: CLABCONF0: =SB-MCM8M
C356 = 10nF,_25V,_X7R,_10%,_0402: CLABCONF0: =SB-MCM8M
C357 = 2.2nF,_50V,_X7R,_10%,_0402_3: CLABCONF0: =SB-MCM8M
C358 = 47uF,6.3V,X5R: CLABCONF0: =SB-MCM8M
C359 = Cap.,22uF,25V,_0805: CLABCONF0: =SB-MCM8M
C360 = 100nF_0402_25V_1: CLABCONF0: =SB-MCM8M
C361 = 100nF_0402_25V_3: CLABCONF0: =SB-MCM8M
C362 = 2.2nF,_50V,_X7R,_10%,_0402_4: CLABCONF0: =SB-MCM8M
D3 D6 D11 = Diode_Shotky,5A,30V: CLABCONF0: =SB-MCM8M
D5 = Diode_,TVS_,15V,1500W_0: CLABCONF0: =SB-MCM8M; P/N: 132D00150S
DS1 DS2 = LED-GREEN_1206_3: CLABCONF0: =SB-MCM8M
E6 = HDR_1x2_100MIL_TH_JUMPER_2: CLABCONF0: =SB-MCM8M
E7 E11 = HDR_1x2_100MIL_TH_JUMPER_1: CLABCONF0: =SB-MCM8M
E4 E8 E19 = HDR_1x2_100MIL_TH_JUMPER: CLABCONF0: =SB-MCM8M
J2 = DC_Jack_,5.5_2_0.5,10A,20V: CLABCONF0: =SB-MCM8M
JP3 JP5 JP13 = Jumper,_black,_100mil: CLABCONF0: =SB-MCM8M
L4 L6 L47 = IND_6.8uH_3.5A: CLABCONF0: =SB-MCM8M; P/N: 147A6R801S
L5 = IND_DELTA_MPL73-2R2_2.2uH_14A: CLABCONF0: =SB-MCM8M
Q2 = P-MOSFET,3A,20V,110mOhm@-1.8V: CLABCONF0: DNP
R107 = 100K,_0402_1: CLABCONF0: =SB-MCM8M; P/N: 161C44221S
R108 = 100K,_1%,_0402,_1_16W_1: CLABCONF0: =SB-MCM8M
R109 = 1K,1%,0402,1_16W: CLABCONF0: =SB-MCM8M; Group: CAN
R110 = 40.2k_,1%: CLABCONF0: =SB-MCM8M
R111 = 10K,1%,0402,1_16W_11: CLABCONF0: =SB-MCM8M
R112 R148 = 47K,_0402: CLABCONF0: =SB-MCM8M; P/N: 161C68001S
R114 = 100K,_1%,_0402,_1_16W_2: CLABCONF0: =SB-MCM8M
R115 = 100K,_1%,_0402,_1_16W: CLABCONF0: =SB-MCM8M
R116 = 100K,_0402: CLABCONF0: =SB-MCM8M; P/N: 161C21531S
R117 = 100K,_0402_2: CLABCONF0: =SB-MCM8M; P/N: 161C49921S
R118 = 240R_resistor,_%0.5: CLABCONF0: DNP; P/N: 161C24003S
R119 = 0R: CLABCONF0: =SB-MCM8M; P/N: 161HR0081S
R120 = 32.4K,_0402: CLABCONF0: =SB-MCM8M; P/N: 161C32421S
R121 = 10K,1%,0402,1_16W_2: CLABCONF0: DNP
R123 = 40.2k_,1%_2: CLABCONF0: =SB-MCM8M
R124 R224 = 10K,1%,0402,1_16W_5: CLABCONF0: =SB-MCM8M
R125 = 4.99K,1%,0402,1_16W_1: CLABCONF0: =SB-MCM8M; P/N: 161C12421S
R126 = 13.3K,_0402_tmp_1: CLABCONF0: =SB-MCM8M; P/N: 161C13321S
R127 = 10K,1%,0402,1_16W_12: CLABCONF0: =SB-MCM8M
R128 R225 R247 R319 = 0R,_0402_1: CLABCONF0: =SB-MCM8M
R129 = 10K,1%,0402,1_16W_8: CLABCONF0: =SB-MCM8M
R130 = 10K,1%,0402,1_16W_14: CLABCONF0: =SB-MCM8M
R131 = 10K,1%,0402,1_16W_9: CLABCONF0: =SB-MCM8M; P/N: 161C16521S
R132 = 33R,5%,0402,1_16W: CLABCONF0: =SB-MCM8M; P/N: 161C64911S
R133 R143 = 0R,_0402_1_5: CLABCONF0: =SB-MCM8M
R134 = 10K,1%,0402,1_16W_13: CLABCONF0: =SB-MCM8M
R135 = 953R,1%,0402,1_16W_0: CLABCONF0: =SB-MCM8M; P/N: 161C91011S
R136 = 10K,1%,0402,1_16W_7: CLABCONF0: =SB-MCM8M
R144 R150 R342 = 0R,_0402_1_1: CLABCONF0: =SB-MCM8M
R146 = 13.3K,_0402_tmp: CLABCONF0: =SB-MCM8M; P/N: 161C13321S
R161 = 10K,1%,0402,1_16W_3: CLABCONF0: DNP
R206 = 0R,_0402_1_3: CLABCONF0: DNP
R223 = 10K,1%,0402,1_16W_10: CLABCONF0: DNP
R246 = 1.5K_1%,_0402: CLABCONF0: =SB-MCM8M
R291 = 32.4K,_0402_1: CLABCONF0: =SB-MCM8M; P/N: 161C32421S
R292 = 10K,1%,0402,1_16W_4: CLABCONF0: DNP
R293 R318 = 0R,_0402_1_4: CLABCONF0: =SB-MCM8M
R226 R294 = 0R,_0402_1_2: CLABCONF0: DNP
R295 = 40.2k_,1%_1: CLABCONF0: =SB-MCM8M
R296 = 4.99K,1%,0402,1_16W: CLABCONF0: =SB-MCM8M; P/N: 161C12421S
R263 R297 = 10K,1%,0402,1_16W_6: CLABCONF0: =SB-MCM8M
R299 = 100k,_%1,_0402: CLABCONF0: DNP
S2 = MISC_SHORT_NL: CLABCONF0: DNP
U18 U20 U45 = RT8272,Converter,3A,24V: CLABCONF0: =SB-MCM8M
U19 = RT6239A_B: CLABCONF0: =SB-MCM8M; P/N: 123V08000S
U21-U23 U46 = RT9186A,LDO_,2.5-5_0.5V,500mA: CLABCONF0: =SB-MCM8M
C144 = 100nF,_10V,_X7R,_10%,_0402_13: CLABCONF0: =SB-MCM8M
C152 C381 = 100nF,_10V,_X7R,_10%,_0402_12: CLABCONF0: =SB-MCM8M
C155 = 100nF,_10V,_X7R,_10%,_0402_14: CLABCONF0: =SB-MCM8M
C156 = 100nF,_10V,_X7R,_10%,_0402_15: CLABCONF0: =SB-MCM8M
C330 = 100nF,_10V,_X7R,_10%,_0402_16: CLABCONF0: =SB-MCM8M
JP6 JP8 = Jumper,_black,_100mil_0: CLABCONF0: =SB-MCM8M
P13 = Conn.,_Micro-USB,_B-Type: CLABCONF0: =SB-MCM8M; P/N: 180K00501S
P15 P16 = Ultra_Mini_Serial_Connector: CLABCONF0: =SB-MCM8M
P23 = microSD_push-pull: CLABCONF0: =SB-MCM8M; P/N: 182K01300S
Q6 = MOSFET_N_DUAL_0_0.4A_20V: CLABCONF0: =SB-MCM8M
R137 = 0R,_0402_1_9: CLABCONF0: =SB-MCM8M
R140 = 0R,_0402_1_8: CLABCONF0: =SB-MCM8M
R141 R322 = 0R,_0402_1_3: CLABCONF0: =SB-MCM8M
R142 = 0R,_0402_1_6: CLABCONF0: =SB-MCM8M
R145 = 0R,_0402_1_7: CLABCONF0: =SB-MCM8M
R173 R336 = 100K,_0402: CLABCONF0: =SB-MCM8M; P/N: 161C10031S
R222 = 10K,1%,0402,1_16W_3: CLABCONF0: =SB-MCM8M
R227 = 0R,_0402_1_4: CLABCONF0: DNP
R262 = 10K,1%,0402,1_16W_4: CLABCONF0: =SB-MCM8M
RN6 = RN,8.2K,10P8R@1206: CLABCONF0: DNP
RN7 RN8 RN18 = RN,10K,8P4R@0805: CLABCONF0: =SB-MCM8M
U11 = 74LCX04_sgl_gate_TSSOP-14: CLABCONF0: =SB-MCM8M
U24 = CP2104_0: CLABCONF0: =SB-MCM8M; P/N: 116A00140S
U25 U30 = TXS0102_0: CLABCONF0: =SB-MCM8M; P/N: 116A01020S
U29 = MAX3243E_RS-232_3T5R_BGA: CLABCONF0: =SB-MCM8M
U31 = 24C02,_serial_EE,_2KB,_I2C: CLABCONF0: =SB-MCM8M; P/N: 111S31000S
U38 = IC,FLASH,SPI,128MBit_11: CLABCONF0: =SB-MCM8M; P/N: 111S32100I
C371 = 100nF,_10V,_X7R,_10%,_0402_4: CLABCONF0: =SB-MCM8M; P/N: 151B10400S
C372 = 100nF,_10V,_X7R,_10%,_0402_2: CLABCONF0: =SB-MCM8M; P/N: 151B10400S
C373 = 100nF,_10V,_X7R,_10%,_0402_11: CLABCONF0: =SB-MCM8M; P/N: 151B10400S
C380 = 10uF_10V_20%_0402_1: CLABCONF0: =SB-MCM8M
C382 = 10uF_10V_20%_0402: CLABCONF0: =SB-MCM8M
D12 = Transz_0: CLABCONF0: =SB-MCM8M; P/N: 132D10100S; ROOM: 1
J4 = UFL_con,_0-6GHz_0: CLABCONF0: =SB-MCM8M; P/N: 184C10010S
L48 = Ind_micro_2R2-2.2uH_@_1.8A: CLABCONF0: =SB-MCM8M
P47 = RJ11: CLABCONF0: =SB-MCM8M
Q7 = N-MOSFET,NDS335N,100mOhm@2.5V: CLABCONF0: =SB-MCM8M
R147 = 0R,_0402_1_2: CLABCONF0: =SB-MCM8M
R315 = 10K,1%,0402,1_16W_0_4: CLABCONF0: =SB-MCM8M; P/N: 161C10021S
R316 = 10K,1%,0402,1_16W_0_1: CLABCONF0: =SB-MCM8M; P/N: 161C10021S
R317 = 0R,_0402_0: CLABCONF0: =SB-MCM8M; P/N: 161C00005S
R320 = 0R,_0402_0_2: CLABCONF0: DNP; P/N: 161C00005S
R323 = 10K,1%,0402,1_16W_0_3: CLABCONF0: =SB-MCM8M; P/N: 161C10021S
R324 = 0R,_0402_0_4: CLABCONF0: =SB-MCM8M; P/N: 161C00005S
R325 = 1M_,5%,_0402: CLABCONF0: =SB-MCM8M; P/N: 161C82511S
R326 = 0R,_0402_0_7: CLABCONF0: =SB-MCM8M; P/N: 161C00005S
R327 = 0R,_0402_0_3: CLABCONF0: DNP; P/N: 161C00005S
R328 = RESISTOR: CLABCONF0: =SB-MCM8M; P/N: 161C93111S
R329 = 1K,1%,0402,1_16W_1: CLABCONF0: =SB-MCM8M
R330 = 120R_1%,_0603: CLABCONF0: =SB-MCM8M
R332 = 0R,_0402_0_1: CLABCONF0: =SB-MCM8M
R333 = 1K,1%,0402,1_16W: CLABCONF0: =SB-MCM8M
R334 = 0R,_0402_0_6: CLABCONF0: =SB-MCM8M
R335 = 0R,_0402_0_5: CLABCONF0: = DNP
R338 = 0R,_0402_0_8: CLABCONF0: =SB-MCM8M; P/N: 161C00005S
R339 = 10K,1%,0402,1_16W_0_2: CLABCONF0: DNP
R340 = 10K,1%,0402,1_16W_0: CLABCONF0: =SB-MCM8M; P/N: 161C10021S
U53 = TXS02612_1: CLABCONF0: =SB-MCM8M; P/N: 116A00200S
U54 = Sterling-LWB5: CLABCONF0: =SB-MCM8M; P/N: 116B00470S
U55 = OSC.,_26.000MHz,100PPM,_1_1.8V: CLABCONF0: =SB-MCM8M; P/N: 105I76040S
U56 U57 U59 = TXB0104_2: CLABCONF0: =SB-MCM8M; P/N: 116A01041S
U58 = MAX3491E_RS-485_DRVR: CLABCONF0: =SB-MCM8M
X7 = XTAL,_32.768KHZ,_20PPM,_4x1.5mm: CLABCONF0: =SB-MCM8M; P/N: 141B32301I

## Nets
1V8_PER_EN_H: Q7.1(G) R338.1 R339.1
1V8_WL: C364.1 R146.2 R324.2 U46.7(Vout1) U46.8(Vout2)
3V3_AW: C22.1 C90.1 C91.1 C92.1 C93.1 C94.1 C95.1 C96.1 C104.2 C129.1 C143.1 C145.1 C146.1 C147.1 C148.1 C149.1 C150.1 C152.1 C153.1 C155.2 C158.2 C185.1 C200.1 C330.1 E11.1 FB2.1 L6.2 P11.2(+3.3V_1) P11.24(+3.3V_AUX) P11.39(RSVD6) P11.41(RSVD7) P11.52(+3.3V_2) P23.P4(VDD) R9.1 R83.2 R95.2 R97.2 R113.1 R120.2 R138.1 R148.1 R206.2 R210.1 R216.1 R224.1 R225.2 R226.2 R227.2 R248.1 R261.1 R262.1 R263.1 R320.2 RN5.6(RC2) RN5.7(RB2) RN6.5(COM1) RN6.10(COM2) RN8.1(RA1) RN8.2(RB1) U17.1(VDDXD) U25.3(VCCA) U27.5(VBUS) U28.5(VBUS) U29.21(FORCEOFF) U29.22(FORCEON) U29.26(VCC3) U30.3(VCCA) U30.7(VCCB) U31.8(VCC) U38.8(VCC) ; also on sheet 1 3 4 5 6 7 13 14
3V3_AW_BOOT: C126.1 U20.1(BOOT)
3V3_AW_CMP: C128.1 C133.1 U20.6(COMP)
3V3_AW_EN: R121.2 U20.7(EN)
3V3_AW_FB: R120.1 R125.1 U20.5(FB)
3V3_AW_RC: C128.2 R123.1
3V3_AW_SS: C132.1 U20.8(SS)
3V3_AW_SW: C126.2 D6.CATHODE L6.1 U20.3(SW)
3V3_DBGUART232_RXD: U29.18(R1OUT) U30.1(B2)
3V3_DBGUART232_TXD: U29.12(T1IN) U30.8(B1)
3V3_DBGUARTUSB_RXD: U24.20(RXD) U25.1(B2)
3V3_DBGUARTUSB_TXD: U24.21(TXD) U25.8(B1)
3V3_WL: C358.1 L47.2 R291.2 R317.2 ; also on sheet 14
5V0_PER: C112.1 L4.2 R107.1 ; also on sheet 1 5 14
5V0_PER_BOOT: C110.1 U18.1(BOOT)
5V0_PER_CMP: C111.1 C116.1 U18.6(COMP)
5V0_PER_EN: R109.2 R161.2 U18.7(EN)
5V0_PER_FB: R107.2 R111.1 U18.5(FB)
5V0_PER_RC: C111.2 R110.1
5V0_PER_SS: C115.1 U18.8(SS)
5V0_PER_SW: C110.2 D3.CATHODE L4.1 U18.3(SW)
GND: BH1.2N(-) C22.2 C51.2 C52.2 C53.2 C54.1 C82.1 C90.2 C91.2 C92.2 C93.2 C94.2 C95.2 C96.2 C97.2 C98.2 C99.2 C103.2 C104.1 C105.1 C106.2 C107.2 C108.2 C109.2 C112.2 C113.2 C114.2 C115.2 C116.2 C117.2 C118.2 C119.2 C121.1 C122.1 C129.2 C130.2 C131.2 C132.2 C133.2 C134.2 C135.2 C136.2 C137.2 C138.2 C139.2 C140.2 C141.2 C142.2 C143.2 C144.2 C145.2 C146.2 C147.2 C148.2 C149.2 C150.2 C152.2 C153.2 C154.2 C155.1 C157.2 C158.1 C172.1 C185.2 C186.2 C187.1 C188.2 C196.1 C197.1 C198.2 C200.2 C245.2 C278.2 C330.2 C358.2 C359.2 C360.2 C361.2 C362.2 C363.2 C364.2 C371.1 C372.1 C373.1 C375.2 C376.2 C377.2 C378.2 C379.2 C380.2 C381.2 C383.2 C384.2 C385.2 C386.2 D3.ANODE D5.ANODE D6.ANODE D11.ANODE D12.2 DS1.CATHODE E4.2 E19.1 J2.2(R) J2.3(Plastic) J2.SH1 J2.SH2 J2.SH3 J2.SH4 J4.2(GND) J4.3(GND) J4.4(GND) L3.5(GND) L3.6(GND) L42.5(GND) L42.6(GND) L43.5(GND) L43.6(GND) L44.5(GND) L44.6(GND) L45.5(GND) L45.6(GND) L46.5(GND) L46.6(GND) P11.4(GND7) P11.9(GND1) P11.15(GND2) P11.18(GND8) P11.21(GND3) P11.26(GND9) P11.27(GND4) P11.29(GND5) P11.34(GND10) P11.35(GND6) P11.37(RSVD5) P11.40(GND11) P11.50(GND12) P12.5(GND) P12.9(M9) P12.10(M10) P12.11(M11) P12.12(M12) P13.5(GND) P13.6(SHIELD1) P13.7(SHIELD2) P13.8(SHIELD3) P13.9(SHIELD4) P15.8 P15.9(CHASSIS) P15.10(CHASSIS) P15.11(CHASSIS) P15.12(CHASSIS) P16.8 P16.9(CHASSIS) P16.10(CHASSIS) P16.11(CHASSIS) P16.12(CHASSIS) P22.6 P22.9 P22.12 P22.15 P22.18 P22.21 P22.22 P22.24 P22.29 P22.30 P23.G1 P23.G2 P23.G3 P23.G4 P23.P6(VSS) P23.SH1 P23.SH2 P47.2 P47.5 Q2.3(D) Q6.1(S1) Q6.4(S2) Q7.2(S) R36.2 R75.2 R85.2 R86.2 R87.2 R98.2 R99.2 R100.1 R101.2 R102.2 R103.2 R104.2 R105.2 R106.2 R108.2 R110.2 R111.2 R115.1 R123.2 R125.2 R127.2 R132.1 R136.2 R149.1 R173.2 R219.1 R295.2 R296.2 R299.1 R300.2 R315.1 R326.2 R328.2 R333.2 R339.2 R340.1 RN5.8(RA2) RN7.1(RA1) RN7.2(RB1) RN7.3(RC1) RN7.4(RD1) RN8.3(RC1) RN18.6(RC2) RN18.7(RB2) RN18.8(RA2) S2.2 U15.2(GND) U17.9(GNDXD) U17.16(GNDODA) U18.4(GND) U18.9(PAD) U19.9(GND) U19.10(GND) U19.11(GND) U19.12(GND) U20.4(GND) U20.9(PAD) U21.5(GND) U21.9(EPAD) U22.5(GND) U22.9(EPAD) U23.5(GND) U23.9(EPAD) U24.2(GND) U25.2(GND) U26.2(GND) U27.2(GND) U28.2(GND) U29.4(R4IN) U29.5(R5IN) U29.24(GND) U29.33(EPAD) U30.2(GND) U31.4(GND) U38.4(GND) U38.9(EPAD) U45.4(GND) U45.9(PAD) U46.5(GND) U46.9(EPAD) U53.2(GND2) U53.11(GND11) U53.25(GND25) U54.1(GND1) U54.2(GND2) U54.3(GND3) U54.4(GND4) U54.5(GND5) U54.8(GND6) U54.9(GND7) U54.10(GND8) U54.11(GND9) U54.12(GND10) U54.16(GND11) U54.18(GND51) U54.20(GND50) U54.26(GND12) U54.30(GND13) U54.35(GND14) U54.38(GND15) U54.40(GND16) U54.45(GND49) U54.48(GND17) U54.53(GND18) U54.54(GND19) U54.55(GND20) U54.56(GND21) U54.57(GND22) U54.58(GND23) U54.60(GND24) U54.61(GND25) U54.62(GND26) U54.63(GND27) U54.64(GND28) U54.65(GND29) U54.66(GND30) U54.67(GND31) U54.68(GND32) U54.69(GND33) U54.70(GND34) U54.71(GND35) U54.72(GND36) U54.73(GND37) U54.74(GND38) U54.75(GND39) U54.76(GND40) U54.77(GND41) U54.78(GND42) U54.79(GND43) U54.80(GND44) U54.81(GND45) U54.82(GND46) U54.83(GND47) U54.84(GND48) U55.2(GND) U56.B4(GND) U57.B4(GND) U58.6(GND) U58.7(GND) U59.B4(GND) X3.2 X3.4 ; also on sheet 1 3 4 5 6 7 13 14
V3P3_Q7_PCIECLK_A: C105.2 FB2.2 U17.15(VDDODA)
VCC_RTC: C198.1 E6.2 ; also on sheet 3
32KHZ_WLANCLK: R187.2 U54.27(RTC_LPO_IN)
100MHz_CLK_S0: RN5.3(RC1) U17.2(S0)
100MHz_CLK_S1: RN5.2(RB1) U17.3(S1)
100MHz_CLK_SS2: RN5.1(RA1) U17.4(SS2)
100MHz_IREF: R100.2 U17.10(IREF)
ANT: C374.2 U54.59(ANT)
ANT_OUT: C374.1 D12.1 R147.2 TP18.1
ANT_OUTT: J4.1(SIG) R147.1
BCKLIGHT_FB: D7.2(ANODE) R41.2 U15.3(FB)
BT_REG_ON: R325.1 R328.1 U54.29(BT_REG_ON)
BT_WAKE_DEV: U54.47(BT_DEV_WAKE) U57.A4
BT_WAKE_HOST: U54.46(BT_HOST_WAKE) U57.A3
CARRIER_3V3_GPIO0_5: R176.2 ; also on sheet 7
CARRIER_3V3_GPIO0_7: R180.2 ; also on sheet 7
CARRIER_EEPROM_WP: E11.2 R149.2 U31.7(WP)
CLK_OE: R95.1 U17.8(OE)
CLK_PD#: R97.1 U17.7(PD#)
DBG_UART_RXD: U25.5(A1) U30.4(A2) ; also on sheet 3
DBG_UART_TXD: U25.4(A2) U30.5(A1) ; also on sheet 3
DEBUGSEL: E4.1 Q6.2(G1) R222.2 RN8.6(RC2) ; also on sheet 7
DISP_IO: C54.2 C188.1 P22.27 R82.1 R83.1 R139.1
DISP_PWRA: C53.1 C187.2 P22.28 R138.2
DISP_RESET: P22.26 R75.1 R215.1 ; also on sheet 7
DSI_CKN: L44.3 ; also on sheet 3
DSI_CKP: L44.4 ; also on sheet 3
DSI_CN: L44.2 P22.13
DSI_CP: L44.1 P22.14
DSI_DN0: L42.3 ; also on sheet 3
DSI_DN1: L43.3 ; also on sheet 3
DSI_DN2: L45.3 ; also on sheet 3
DSI_DN3: L46.3 ; also on sheet 3
DSI_DP0: L42.4 ; also on sheet 3
DSI_DP1: L43.4 ; also on sheet 3
DSI_DP2: L45.4 ; also on sheet 3
DSI_DP3: L46.4 ; also on sheet 3
DSI_N0: L42.2 P22.7
DSI_N1: L43.2 P22.10
DSI_N2: L45.2 P22.16
DSI_N3: L46.2 P22.19
DSI_P0: L42.1 P22.8
DSI_P1: L43.1 P22.11
DSI_P2: L45.1 P22.17
DSI_P3: L46.1 P22.20
EPR_A0: R226.1 RN7.8(RA2) U31.1(A0)
EPR_A1: R227.1 RN7.7(RB2) U31.2(A1)
EPR_A2: R225.1 RN7.6(RC2) U31.3(A2)
EXTLDO_EN: R297.2 R299.2 U46.4(EN)
FB_LDO_1V5: R135.1 R136.1 U23.6(ADJ)
FB_LDO_1V8: R126.1 R127.1 U21.6(ADJ)
FB_LDO_2V8: R131.1 R132.2 U22.6(ADJ)
FB_WL_1V8: R146.1 R300.1 U46.6(ADJ)
FPC_GND: P45.1 P45.8 R219.2 U32.2(GND)
FPC_INT: P45.6 R176.1 R220.2 U32.3(IO2)
FPC_PWR: C186.1 P45.3 R216.2 U32.5(VBUS)
FPC_RES: P45.7 R221.2 U32.1(IO1)
FPC_SCL: P45.4 R218.2 U32.4(IO3)
FPC_SDA: P45.5 R217.2 U32.6(IO4)
GPIO1_I13: R211.1 ; also on sheet 3
I2C1_SCL: U31.6(SCL) ; also on sheet 3 7
I2C1_SDA: U31.5(SDA) ; also on sheet 3 7
I2C4_SCL: P11.30(SMB_CLK) R218.1 ; also on sheet 6 7
I2C4_SDA: P11.32(SMB_DATA) R217.1 ; also on sheet 6 7
IDT_CLK0_N: R89.1 U17.19(CLK0_N)
IDT_CLK0_P: R88.1 U17.20(CLK0_P)
IDT_CLK1_N: R91.1 U17.17(CLK1_N)
IDT_CLK1_P: R90.1 U17.18(CLK1_P)
IDT_CLK2_N: R93.1 U17.13(CLK2_N)
IDT_CLK2_P: R92.1 U17.14(CLK2_P)
IDT_CLK3_N: R96.1 U17.11(CLK3_N)
IDT_CLK3_P: R94.1 U17.12(CLK3_P)
IDT_CLK_X1: C106.1 U17.5(X1/ICLK) X3.1
IDT_CLK_X2: C107.1 U17.6(X2) X3.3
IDT_T_CLK1_N: P11.11(REFCLK-) R85.1 R91.2 R103.1
IDT_T_CLK1_P: P11.13(REFCLK+) R86.1 R90.2 R102.1
IDT_T_CLK2_N: R93.2 R105.1 ; also on sheet 14
IDT_T_CLK2_P: R92.2 R106.1 ; also on sheet 14
IDT_T_CLK3_N: R96.2 R99.1
IDT_T_CLK3_P: R94.2 R104.1
LCDINT_GPIO1_IO1: R220.1 ; also on sheet 3 14
LED_A: C278.1 D2.CATHODE D7.1(CATHODE) P22.4 U15.5(OVP)
LED_EN: R180.1 R211.2 R229.2 U15.4(EN/PWM)
LED_K: P22.2 R39.1 R41.1
LED_USBSERIALEN: R150.2 U11.13(I)
mPCIe_PERST: P11.22(PERST#) R87.1 R192.2 ; also on sheet 7
mPCIE_USB_DN: L3.4 P11.36(USB_D-)
mPCIE_USB_DP: L3.3 P11.38(USB_D+)
MUX_PCI_USB_DN: L3.1 ; also on sheet 5
MUX_PCI_USB_DP: L3.2 ; also on sheet 5
nUSBSERIALEN: Q6.5(G2) Q6.6(D1) RN8.8(RA2) U30.6(OE)
P_AGND: C124.2 C125.2 R117.2 S2.1 U19.1(AGND)
PCI_1V5: C97.1 C98.1 C99.1 C103.1 P11.6(+1.5V_1) P11.28(+1.5V_2) P11.48(+1.5V_3) R228.2
PCIE1_REF_CLKN: R89.2 R98.1 ; also on sheet 3
PCIE1_REF_CLKP: R88.2 R101.1 ; also on sheet 3
PCIE1_RXN_N: P11.23(PER_N0) ; also on sheet 3
PCIE1_RXN_P: P11.25(PER_P0) ; also on sheet 3
PCIE1_TXN_N: P11.31(PET_N0) ; also on sheet 3
PCIE1_TXN_P: P11.33(PET_P0) ; also on sheet 3
PMIC_ON_REQ: R109.1 R144.2 ; also on sheet 3 14
POR_B: R192.1 R207.2 R215.2 ; also on sheet 3 7 13 14
QSPIA_DATA0: R263.2 U38.5(SI(IO0)) ; also on sheet 3
QSPIA_DATA1: R262.2 U38.2(SO(IO1)) ; also on sheet 3
QSPIA_DATA2: R261.2 U38.3(WP#(IO2)) ; also on sheet 3
QSPIA_DATA3: R248.2 U38.7(HOLD#(IO3)) ; also on sheet 3
QSPIA_nSS0: R224.2 U38.1(CS#) ; also on sheet 3
QSPIA_SCLK: R173.1 U38.6(SCK) ; also on sheet 3
RS232_RXD_UART2: P16.3 U29.2(R2IN)
RS232_TXD_UART2: P16.1 U29.7(T2OUT)
RS232DB_LED: DS2.ANODE R148.2
RS232DB_LEDCAT: DS2.CATHODE U11.12
RS232DB_RXD_DBG: P15.3 U29.1(R1IN)
RS232DB_TXD_DBG: P15.1 U29.6(T1OUT)
RS485_DE: R331.2 R332.2 R334.2 R335.2 U58.4(DE)
RS485_RE#: R332.1 U58.3(~{RE})
SD1_CLK: U53.9(CLKA) ; also on sheet 3
SD1_CMD: U53.4(CMDA) ; also on sheet 3
SD1_D5: R322.1 U57.C4(B4)
SD1_D6: R321.2 U57.C3(B3)
SD1_D7: R318.1 U57.C2(B2)
SD1_DATA0: U53.6(DAT0A) ; also on sheet 3
SD1_DATA1: U53.7(DAT1A) ; also on sheet 3
SD1_DATA2: U53.1(DAT2A) ; also on sheet 3
SD1_DATA3: U53.3(DAT3A) ; also on sheet 3
SD1_DATA4: R325.2 ; also on sheet 3
SD1_DATA5: R322.2 ; also on sheet 3
SD1_DATA6: R321.1 ; also on sheet 3
SD1_DATA7: R318.2 ; also on sheet 3
SD1_RES: R319.1 U57.C1(B1)
SD1_RESET: R319.2 ; also on sheet 3
SD2_CLK: R143.2 ; also on sheet 3
SD2_CMD: R145.2 ; also on sheet 3
SD2_DATA0: R140.2 ; also on sheet 3
SD2_DATA1: R137.2 ; also on sheet 3
SD2_DATA2: R141.2 ; also on sheet 3
SD2_DATA3: R142.2 ; also on sheet 3
SD2_nCD: P23.P9(CD#) R9.2 ; also on sheet 3
SDCARD_CLK: P23.P5(CLK) R143.1 RN6.7(R6) U27.3(IO2)
SDCARD_CMD: P23.P3(CMD) R145.1 RN6.8(R7) U28.6(IO4)
SDCARD_DAT0: P23.P7(DAT0) R140.1 RN6.1(R1) U27.1(IO1)
SDCARD_DAT1: P23.P8(DAT1) R137.1 RN6.2(R2) U27.6(IO4)
SDCARD_DAT2: P23.P1(DAT2) R141.1 RN6.3(R3) U28.1(IO1)
SDCARD_DAT3: P23.P2(DAT3) R142.1 RN6.4(R4) U28.4(IO3)
SERIAL_VBUS: C142.1 P13.1(VBUS) R222.1 U24.7(REGIN) U24.8(VBUS) U26.4(IO3)
SIM1_CLK: P11.12(UIM_CLK) P12.3(CLK)
SIM1_IO: P11.10(UIM_DATA) P12.7(IO)
SIM1_RST: P11.14(UIM_RESET) P12.2(RST)
SIM1_VCC: C196.2 P11.8(UIM_PWR) P12.1(VCC)
SIM1_VPP: P11.16(UIM_VPP) P12.6(VPP)
SP_PMP_C1N: C156.2 U29.23(C1-)
SP_PMP_C1P: C156.1 U29.28(C1+)
SP_PMP_C2N: C151.2 U29.30(C2-)
SP_PMP_C2P: C151.1 U29.29(C2+)
SP_PMP_VN: C154.1 U29.31(V-)
SP_PMP_VP: C157.1 U29.27(V+)
SRPVSS: C382.1 R326.1 U54.31(SRPVSS) U54.33(SRPVSS1)
TOUCH_RESET: R207.1 R221.1 ; also on sheet 7
TP3: P22.25 TP3.1
TXS0104_U_OE: Q7.3(D) R316.1 U56.B3(OE)
TXS0104_WL_OE: R323.1 U57.B3(OE)
U53_SEL: R315.2 U53.24(SEL)
UART2_485_N: P47.1 P47.6 R330.1 R333.1 U58.10(Z) U58.11(B)
UART2_485_P: P47.3 P47.4 R329.2 R330.2 U58.9(Y) U58.12(A)
UART2_R2OUT: R247.2 U29.17(R2OUT)
UART2_RXD/ECSPI3_MISO: R247.1 ; also on sheet 3 14
UART2_T2IN: R245.2 U29.11(T2IN)
UART2_TXD/ECSPI3_SS0: R245.1 ; also on sheet 3 14
UART4_CTS/ECSPI2_MISO: U56.C1(B1) U59.C1(B1) ; also on sheet 3 14
UART4_RTS/ECSPI2_SS0: U56.C2(B2) U59.C2(B2) ; also on sheet 3 14
UART4_RXD/ECSPI2_SCLK: U56.C4(B4) U59.C4(B4) ; also on sheet 3 14
UART4_SEL: E19.2 R336.1 R338.2 U59.B3(OE) ; also on sheet 7
UART4_TXD/ECSPI2_MOSI: U56.C3(B3) U59.C3(B3) ; also on sheet 3 14
UART_RS485_CTS: R334.1 U59.A1
UART_RS485_RTS: R335.1 U59.A2
UART_RS485_RX: U58.2(RO) U59.A4
UART_RS485_TX: U58.5(DI) U59.A3
USBSERIAL_3V45: C140.1 C141.1 C144.1 RN8.4(RD1) U24.5(VIO) U24.6(VDD) U25.7(VCCB)
USBSERIAL_DN: P13.2(D-) U24.4(DN) U26.6(IO4)
USBSERIAL_DP: P13.3(D+) U24.3(DP) U26.1(IO1)
USBSERIAL_nRST: RN8.5(RD2) U24.9(RST#)
USBSERIALEN: Q6.3(D2) R150.1 RN8.7(RB2) U25.6(OE)
V_LED: C51.1 C52.1 L8.1 R208.2 R210.2 R229.1 U15.6(IN)
V_RTC: C245.1 E6.1 R246.2
V_SOM: C121.2 C122.2 C134.1 C136.1 C138.1 E7.1 E8.1 R112.1 R118.1 R119.2 R129.2 R134.2 R208.1 R223.1 R294.1 U21.1(Vin1) U21.2(Vin2) U22.1(Vin1) U22.2(Vin2) U23.1(Vin1) U23.2(Vin2) ; also on sheet 3 14
V_SOM_BOOT: C120.1 U19.5(BOOT)
V_SOM_DSCHG: Q2.2(S) R118.2
V_SOM_EN: R113.2 R115.2 U19.13(EN) ; also on sheet 14
V_SOM_FB: C123.2 R116.1 R117.1 U19.2(FB)
V_SOM_L: C123.1 C172.2 C197.2 E7.2 E8.2 L5.2 R116.2 R119.1
V_SOM_LX: C120.2 L5.1 U19.6(SW)
V_SOM_PG: Q2.1(G) R114.2 U19.4(PGOOD)
V_SOM_PVCC: C125.1 U19.3(PVCC)
V_SOM_SS: C124.1 U19.14(SS)
VCOIN: BH1.1P(+) BH1.3P(+) R246.1
VDC_IN: C108.1 C109.1 C113.1 C114.1 C117.1 C118.1 C119.1 C130.1 C131.1 C359.1 C360.1 D5.CATHODE J2.1(CENTRAL) R108.1 R114.1 R121.1 R161.1 R292.1 U18.2(Vin) U19.7(VIN) U19.8(VIN) U20.2(Vin) U45.2(Vin)
VLX: L48.1 U54.32(SR_VLX)
VSB_1V5: C139.1 R135.2 R228.1 U23.7(Vout1) U23.8(Vout2) ; also on sheet 7
VSB_1V5_EN: R133.2 R134.1 U23.4(EN)
VSB_1V8: C135.1 R82.2 R124.1 R126.2 R327.2 U21.7(Vout1) U21.8(Vout2) ; also on sheet 7 14
VSB_1V8_EN: C82.2 R144.1 R206.1 R223.2 U21.4(EN)
VSB_1V8_PGOOD: R124.2 R128.2 U21.3(PGOOD)
VSB_2V8: C137.1 R130.1 R131.2 U22.7(Vout1) U22.8(Vout2) ; also on sheet 7
VSB_2V8_EN: R128.1 R129.1 U22.4(EN)
VSB_2V8_PGOOD: R130.2 R133.1 U22.3(PGOOD)
VSOM_LED: DS1.ANODE R112.2
W_PCM_CLK: RN18.2(RB1) U54.42(BT_PCM_CLK)
W_PCM_IN: RN18.3(RC1) U54.41(BT_PCM_IN)
W_PCM_SYNC: RN18.1(RA1) U54.43(BT_PCM_SYNC)
W_UART_CTS: U54.49(BT_UART_CTS) U56.A1
W_UART_RTS: U54.50(BT_UART_RTS) U56.A2
W_UART_RX: U54.52(BT_UART_TXD) U56.A4
W_UART_TX: U54.51(BT_UART_RXD) U56.A3
WL_1V8: C371.2 C373.2 C375.1 C376.1 C378.1 C383.1 R122.1 R139.2 R316.2 R323.2 R324.1 R327.1 R342.1 U53.21(VCCB0) U54.39(VDDIO) U55.5(VDD) U56.B2(VCCA) U57.B2(VCCA)
WL_1V8_IN: C363.1 R293.2 R294.2 R297.1 U46.1(Vin1) U46.2(Vin2)
WL_1V8_VCCB1: R342.2 U53.17(VCCB1)
WL_32XTAL_IN: U55.3(OSCIN) X7.1
WL_32XTAL_OUT: U55.1(OSCOUT) X7.2
WL_CLKEN: R122.2 U55.4(CLKEN)
WL_CLKOUT: R187.1 U55.6(CLKOUT)
WL_REG_ON: R340.2 U54.28(WL_REG_ON) U57.A1
WL_SD_CLK: U53.19(CLKB0) U54.19(SDIO_CLK)
WL_SD_CMD: U53.20(CMDB0) U54.21(SDIO_CMD)
WL_SD_DATA0: U53.18(DAT0B0) U54.22(SDIO_DAT0)
WL_SD_DATA1: U53.16(DAT1B0) U54.23(SDIO_DAT1)
WL_SD_DATA2: U53.23(DAT2B0) U54.24(SDIO_DAT2)
WL_SD_DATA3: U53.22(DAT3B0) U54.25(SDIO_DAT3)
WL_VBAT: C372.2 C377.1 C379.1 C380.1 C381.1 C384.1 C385.1 C386.1 R293.1 R317.1 R320.1 R329.1 R331.1 R336.2 U53.5(VCCA) U54.36(VBAT1) U54.37(VBAT2) U56.B1(VCCB) U57.B1(VCCB) U58.13(VCC) U58.14(VCC) U59.B1(VCCB) U59.B2(VCCA)
WL_VBAT_BOOT: C356.1 U45.1(BOOT)
WL_VBAT_CMP: C357.1 C362.1 U45.6(COMP)
WL_VBAT_EN: R292.2 U45.7(EN)
WL_VBAT_FB: R291.1 R296.1 U45.5(FB)
WL_VBAT_RC: C357.2 R295.1
WL_VBAT_SS: C361.1 U45.8(SS)
WL_VBAT_SW: C356.2 D11.CATHODE L47.1 U45.3(SW)
WL_WAKE_HOST: U54.17(WL_HOST_WAKE) U57.A2
WLAN_LDO: C382.2 L48.2 U54.34(VIN_LDO)
WLD_RES: R36.1 R39.2
WLD_SW: D2.ANODE L8.2 U15.1(LX)

Not connected (* = marked no-connect by the designer): P11 1(WAKE#)* 3(RSVD1)* 5(RSVD2)* 7(CLKREQ#)* 17(RSVD3)* 19(RSVD4)* 20(RSVD18)* 42(LED_WWAN#)* 43(RSVD8)* 44(LED_WLAN#)* 45(RSVD9)* 46(LED_WPAN#)* 47(RSVD10)* 49(RSVD11)* 51(RSVD12)*; P12 4(RSVD4)* 8(RSVD8)*; P13 4(ID)*; P15 2* 4* 5* 6* 7*; P16 2* 4* 5* 6* 7*; P22 1* 3* 5* 23*; P45 2*; RN5 4(RD1)* 5(RD2)*; RN6 6(R5)* 9(R8)*; RN7 5(RD2)*; RN18 4(RD1)* 5(RD2)*; U23 3(PGOOD)*; U24 1(RI)* 10(NC)* 11(GPIO3)* 12(GPIO2)* 13(GPIO1)* 14(GPIO0)* 15(SUSPEND#)* 16(VPP)* 17(SUSPEND)* 18(CTS)* 19(RTS)* 22(DSR)* 23(DTR)* 24(DCD)*; U26 3(IO2)* 5(VBUS)*; U27 4(IO3)*; U28 3(IO2)*; U29 3(R3IN)* 8(T3OUT)* 9(NC)* 10(T3IN)* 13(R5OUT)* 14(R4OUT)* 15(R3OUT)* 16(NC)* 19(R2OUTB)* 20(INVALID)* 25(NC)* 32(NC)*; U46 3(PGOOD)*; U53 8(DAT2B1)* 10(DAT3B1)* 12(CMDB1)* 13(CLKB1)* 14(DAT0B1)* 15(DAT1B1)*; U54 6(RF_SW_CTRL9)* 7(RF_SW_CTRL8)* 13(GPIO_3)* 14(GPIO_5)* 15(GPIO_4)* 44(BT_PCM_OUT)*; U58 1(NC)* 8(NC)*

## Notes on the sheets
sheet 8
- KD050HDFIA020 LCD connector
- diff 100 ohm
- diff 100 ohm
- diff 100 ohm
- diff 100 ohm
- diff 100 ohm
- diff 100 ohm
- diff 100 ohm
- diff 100 ohm
- diff 100 ohm
- diff 100 ohm
- LCD back-light power
- DNP
- Typical LED configuration: Two parallel chains of 6 serially connected LEDs
- DNP
- DNP
- DNP
- DNP
- ALT5-PWM OUT
- KD050HDFIA020 touch-panel connector
- 19V/ 40mA
- provision
- DNP
- DNP
- I2C addres:0xBA/0xBB or 0x28/0x29
  D. Sheet, page 9
- Pinout of J5 reversed
   to FPC
- DNP
sheet 9
- mini PCIe socket & SIM socket
- DNP
- DNP
- Validate if those resistors
  required after bring up
- DNP
- PCIe clock generator
- Make trace to VDD AsShortAsPossible,
  decoupling caps and FB can be placed on back
  and placed ACAP to VDD
- 100 MHzCLK diff pairs
  100 ohm impedance
  28 mil intralane missmatch
sheet 10
- DC input
- 5V0_PER
- MAX 16V
- RTC battery
- min 6.8uH
- 12V domain
- DNP
- H=4.2mm
- Vout=Vfb*(1+Rt/Rb)=
  0.92*(1+32.4/12.4)=3.32V@3A
- Install by default
- 12V domain
- up to 24V
- DNP
- V_SOM
- V_SOM discharge
- 3V3_AW
- Vout = 0.7x(1+Rup/Rdn)=0.7*(1+215/49.9)=3.72@9A
- to 100 mill header
- 12V domain
- H=4.2mm
- Vout=Vfb*(1+Rt/Rb)=
  0.92*(1+32.4/12.4)=3.32V@3A
- DNP
- EN=2.8V
- >1.6V
- DNP
- 12V domain
- Vin 4.5-18V
- 10mA OD
- Current measure
- 12V domain
- Vgs up to 12V
- DNP
- DNP
- VSB_1V5, VSB_1V8 & VCC_2V8 CSI sources
- DNP
- Enable for NEW camera ??
- WiFi Power
- 3V3_VBAT
- DNP
- Vout=Vfb*(1+Rt/Rb)=0.8*(1+13.3/10)=1.86V
- H=4.2mm
- Vout=Vfb*(1+Rt/Rb)=
  0.92*(1+32.4/12.4)=3.32V@3A
- DNP
- EN=2.8V
- DNP
- 12V domain
- DNP
- Vout=Vfb*(1+Rt/Rb)=0.8*(1+16.5/6.49)=2.8V
- VIO 1V8
- DNP
- Vout=Vfb*(1+Rt/Rb)=0.8*(1+9.1/10)=1.528V
- Vout=Vfb*(1+Rt/Rb)=0.8*(1+13.3/10)=1.86V
- 500mA
- DNP
sheet 11
- Micro-SD socket (bootable)
- Serial debug console
- DNP
- DEBUG PORT
  (microUSB2.0 Type B)
  UART over USB
- In
- Out
- O
- DNP
- O
- USB console connection indicator
- Jumper removed: Automatic Mode
      Debug over USB when USB host
  provides VBUS
      Debug over RS-232 when USB VBUS not
  available
  Jumper assembled: Force RS232
- TX-Out
- RX-In
- Carrier-board EEPROM
- RS232
- DEBUG PORT
  (Compulab Proprietry)
  UART over RS-232
- 3.3V x 2mA = 6.6mW
- I2C slave address: 0x54..0x57
- RS-232
sheet 12
- WiFi/BT 802.11a/b/g/n/ac + Bluetooth 4.1/ EDR
- NVCC_SD1=1.8V
- Internal PUs
- Internal PUs
- Low B0/High B1
  WiFi default (low)
- Power consumption: <1mA
- LEVEL SHIFTERS
- According to EM7604 DS, no caps needed on XTAL
- OE VCCA
  domain
- WLAN PWR
- LEVEL SHIFTERS
- DNP
- OE VCCA
  domain
- 0402
- DNP
- RS485
- FM-SER PINOUT
  SINGLE RJ11
- LEVEL SHIFTERS
- Active low
- OE VCCA
  domain
- RTS left as provision
- DNP
